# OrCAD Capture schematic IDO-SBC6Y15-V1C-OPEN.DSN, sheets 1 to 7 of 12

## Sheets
1 P01 NOTE: title: IDO-EVB6Y08-V1; note: NOTE
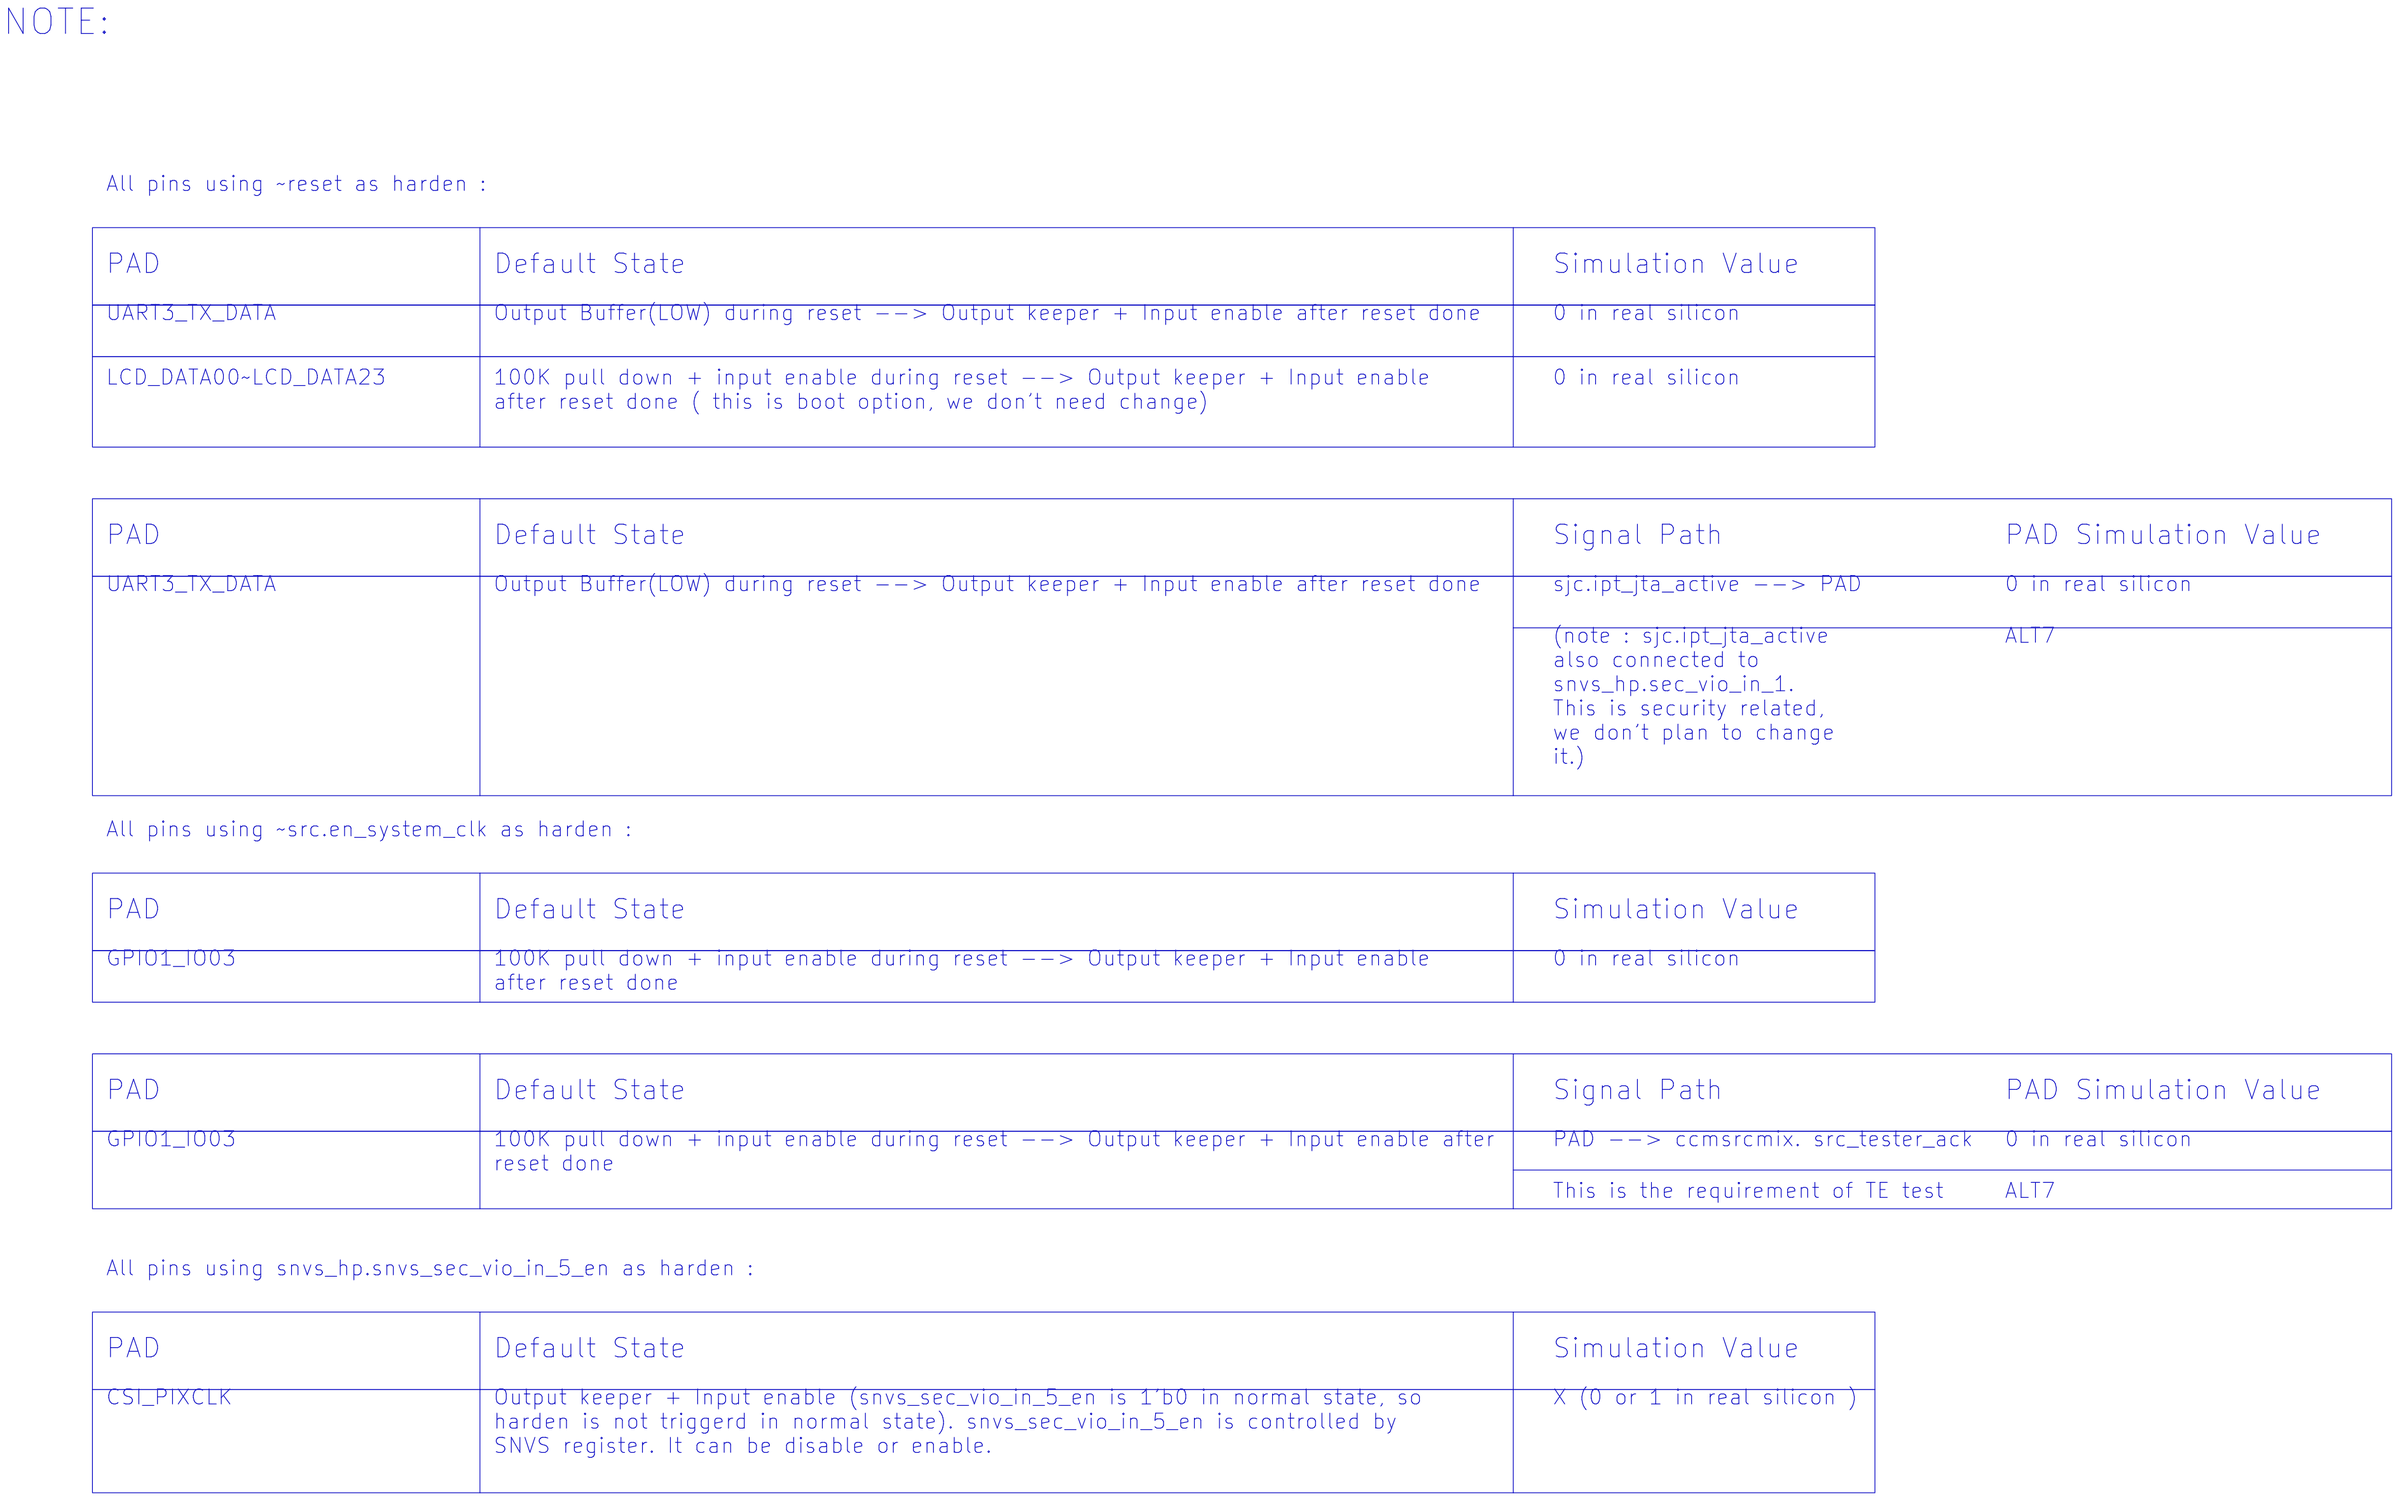
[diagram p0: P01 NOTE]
2 P02 IOMUX: note: IOMUX
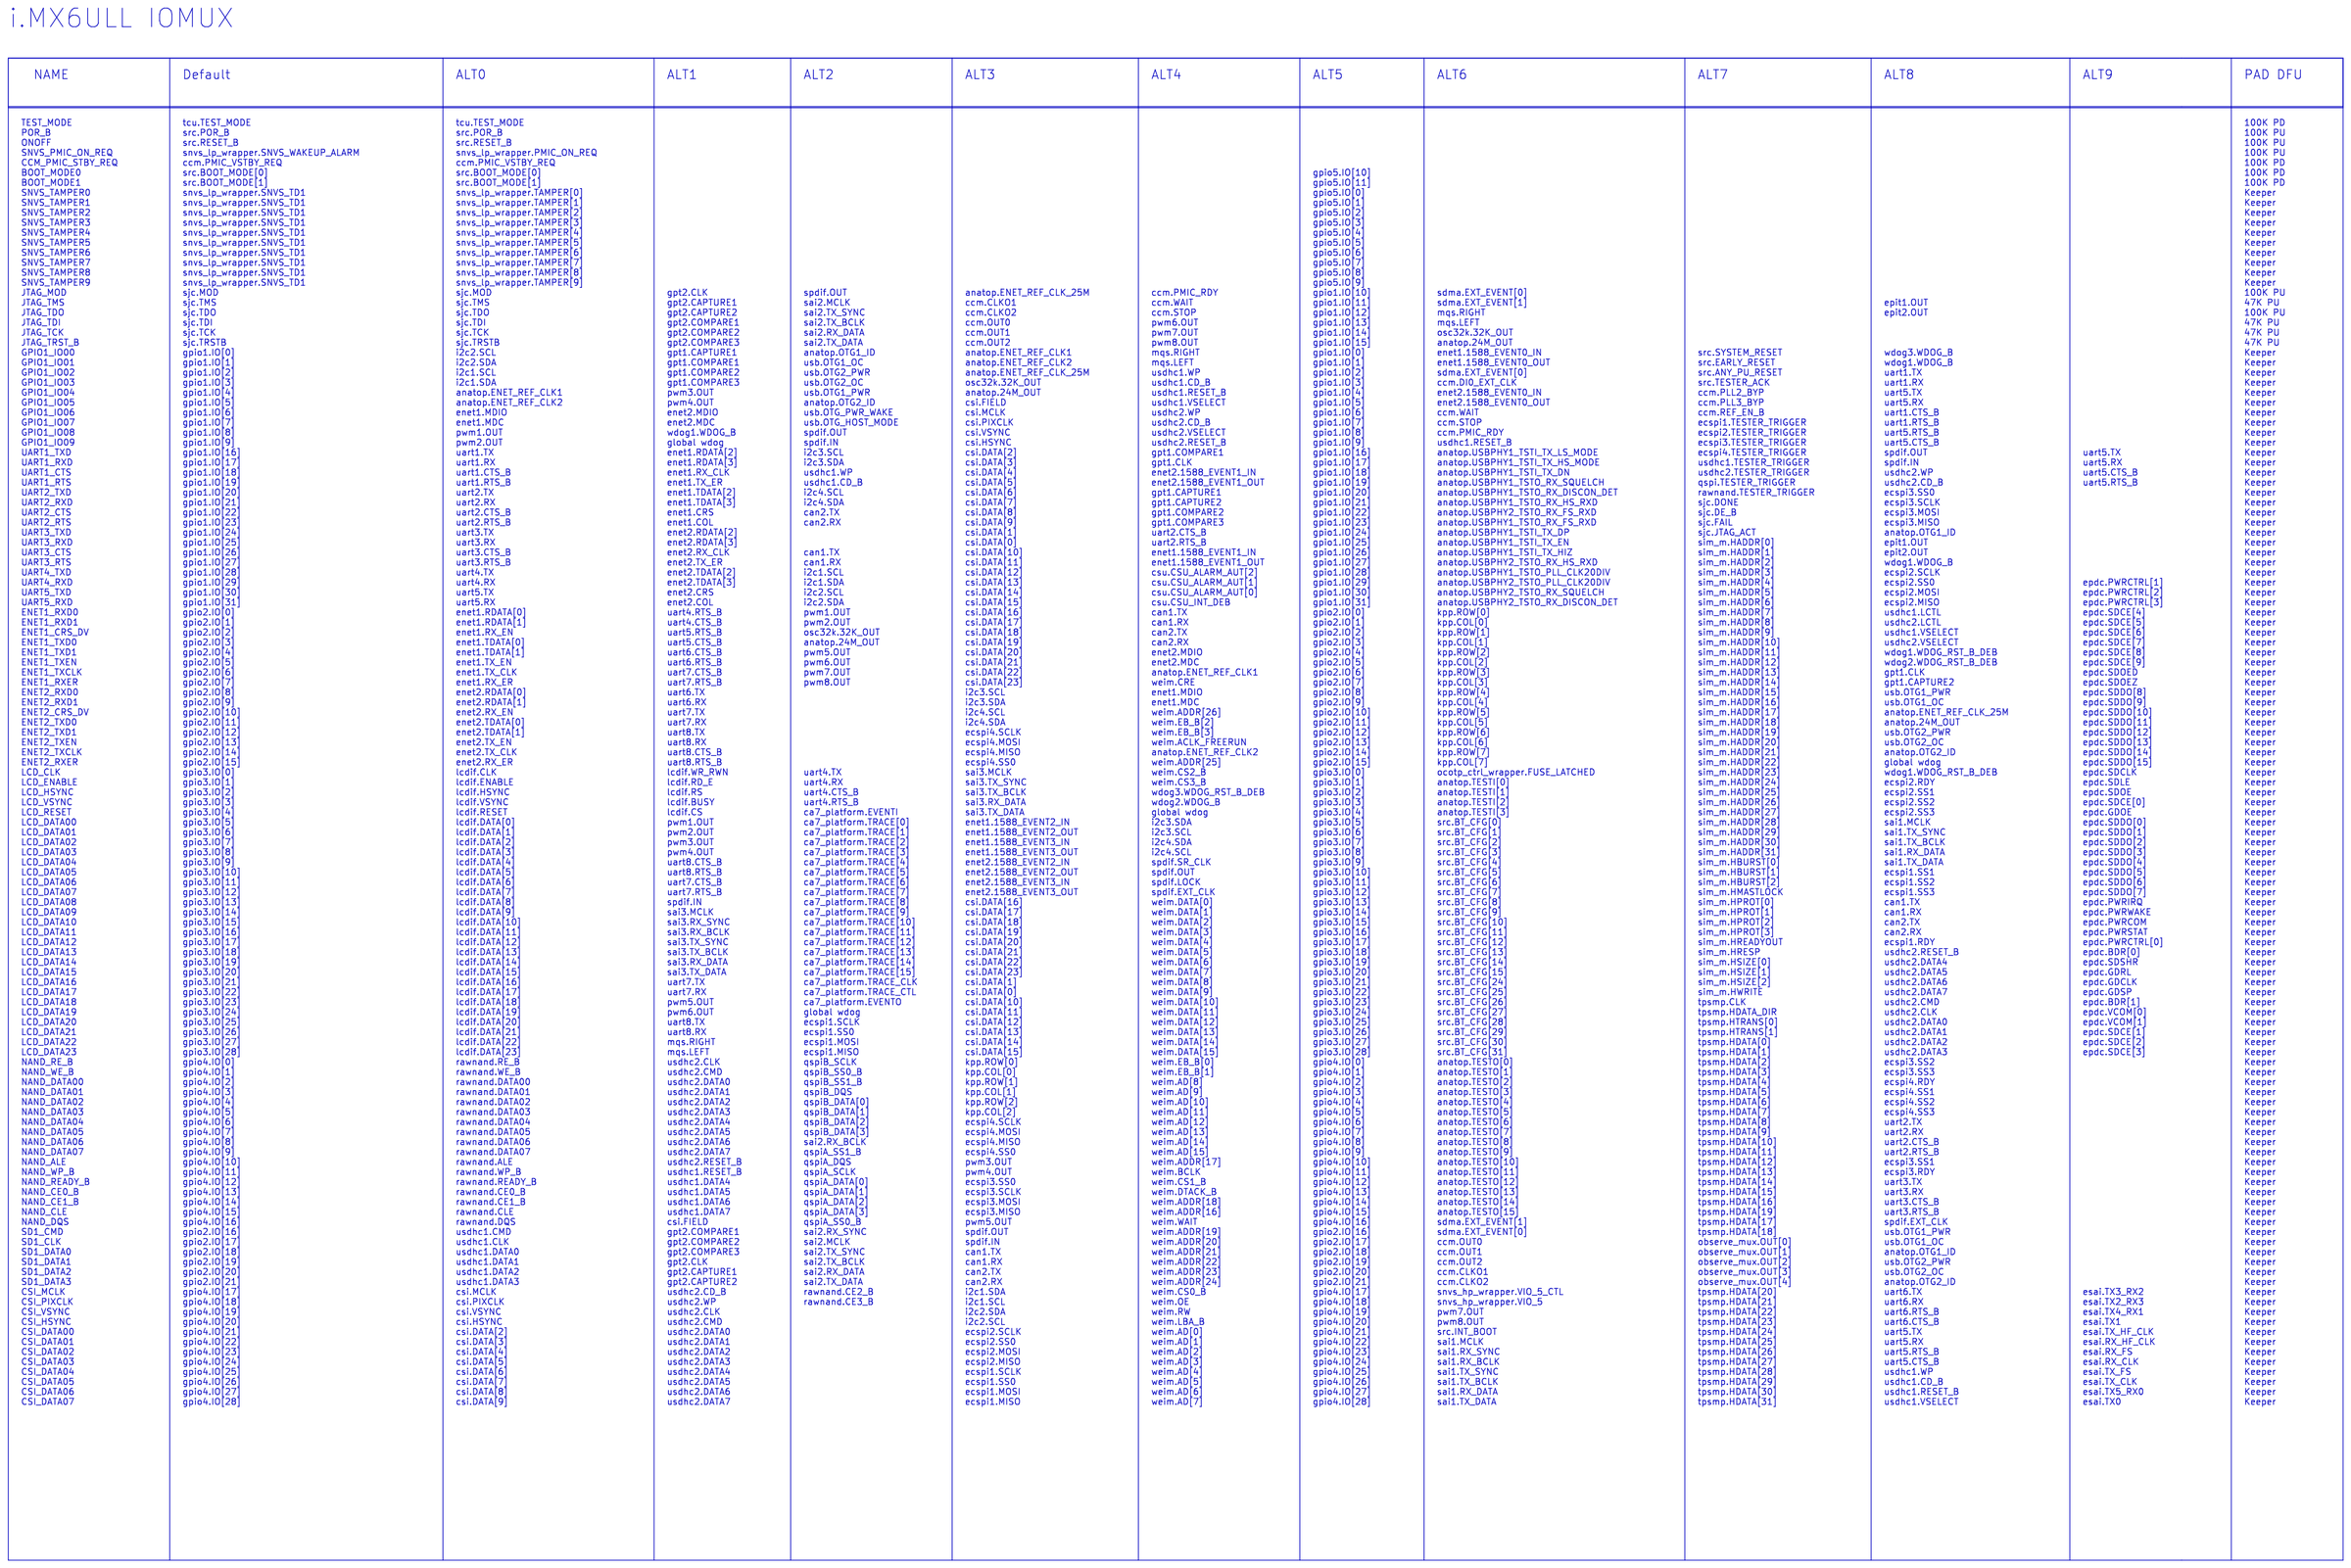
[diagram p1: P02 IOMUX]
3 P03 POWER TREE: note: POWER TREE
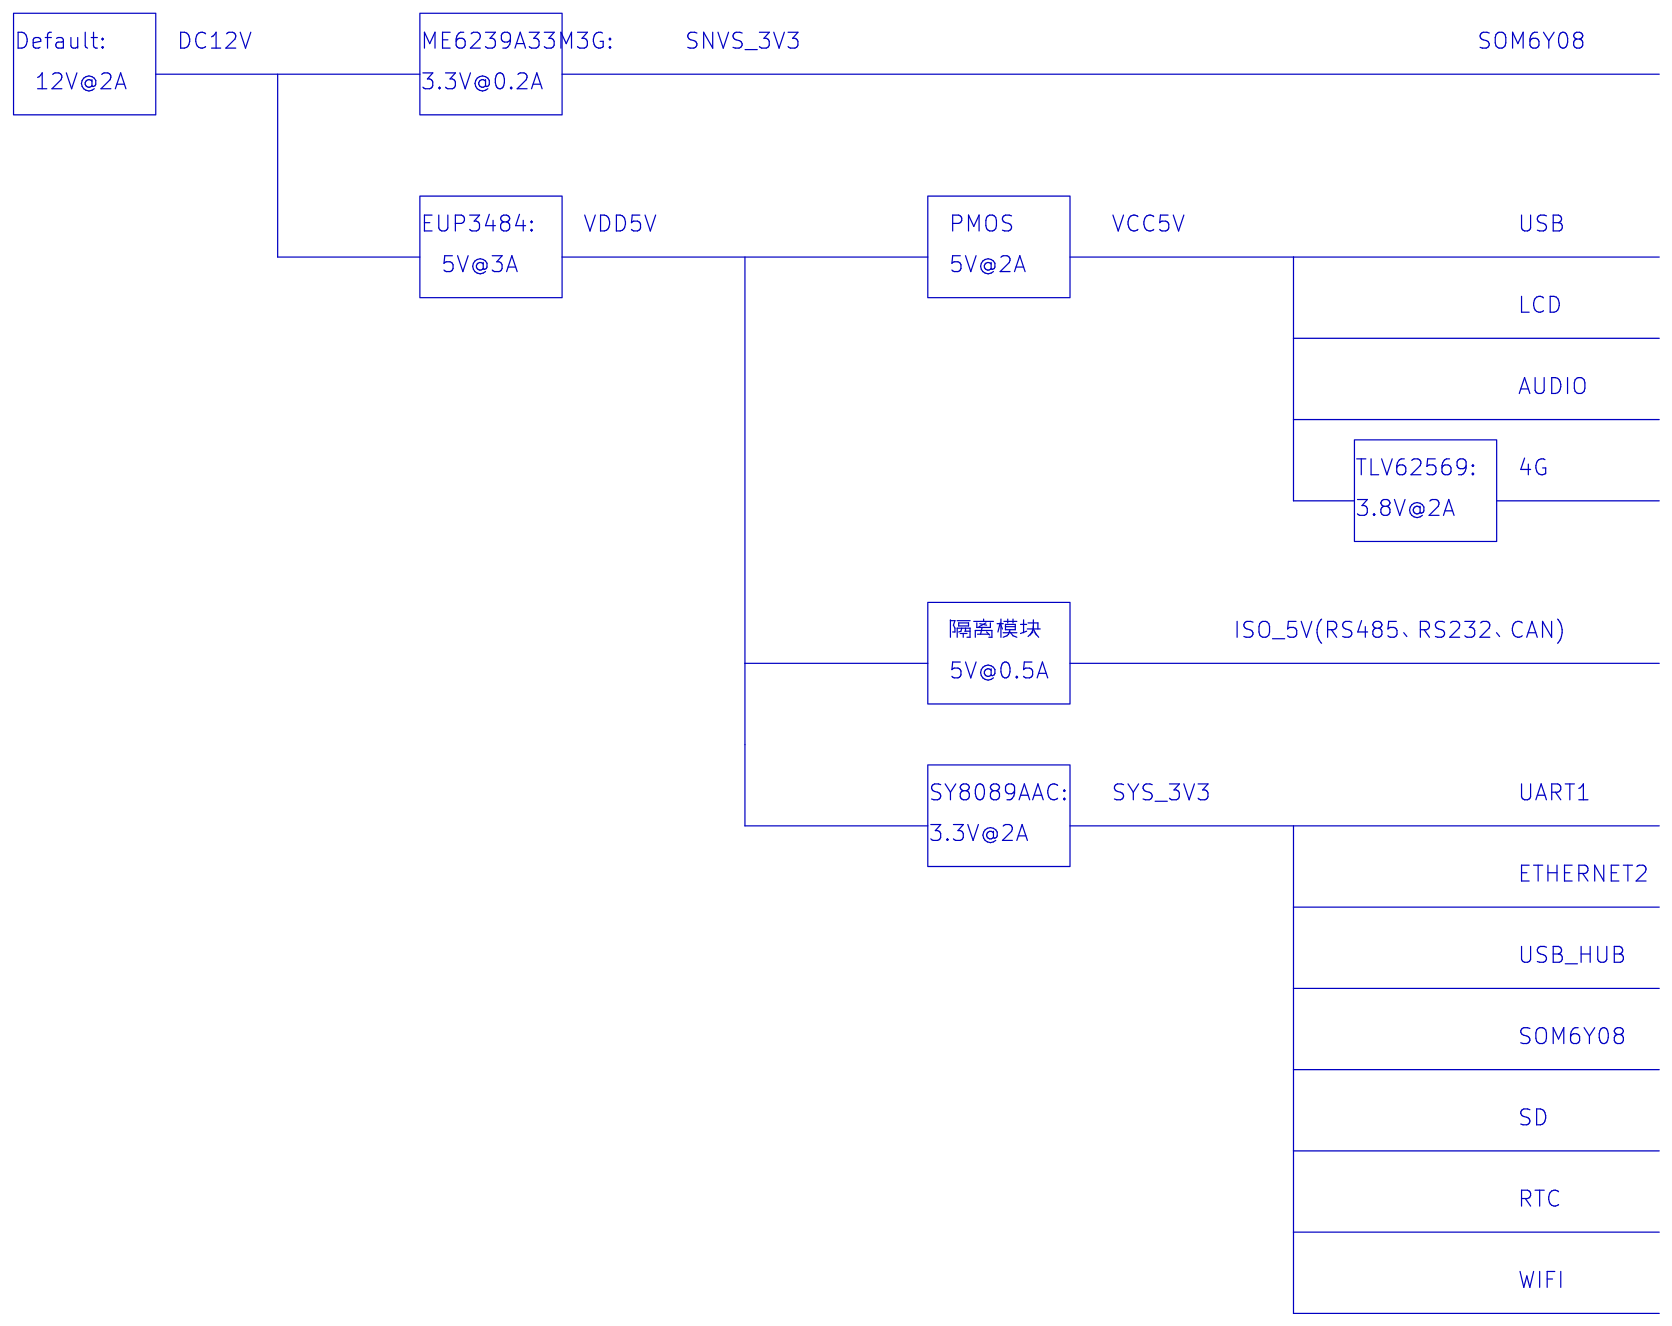
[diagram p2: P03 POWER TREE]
4 P04 BLOCK: note: BLOCK
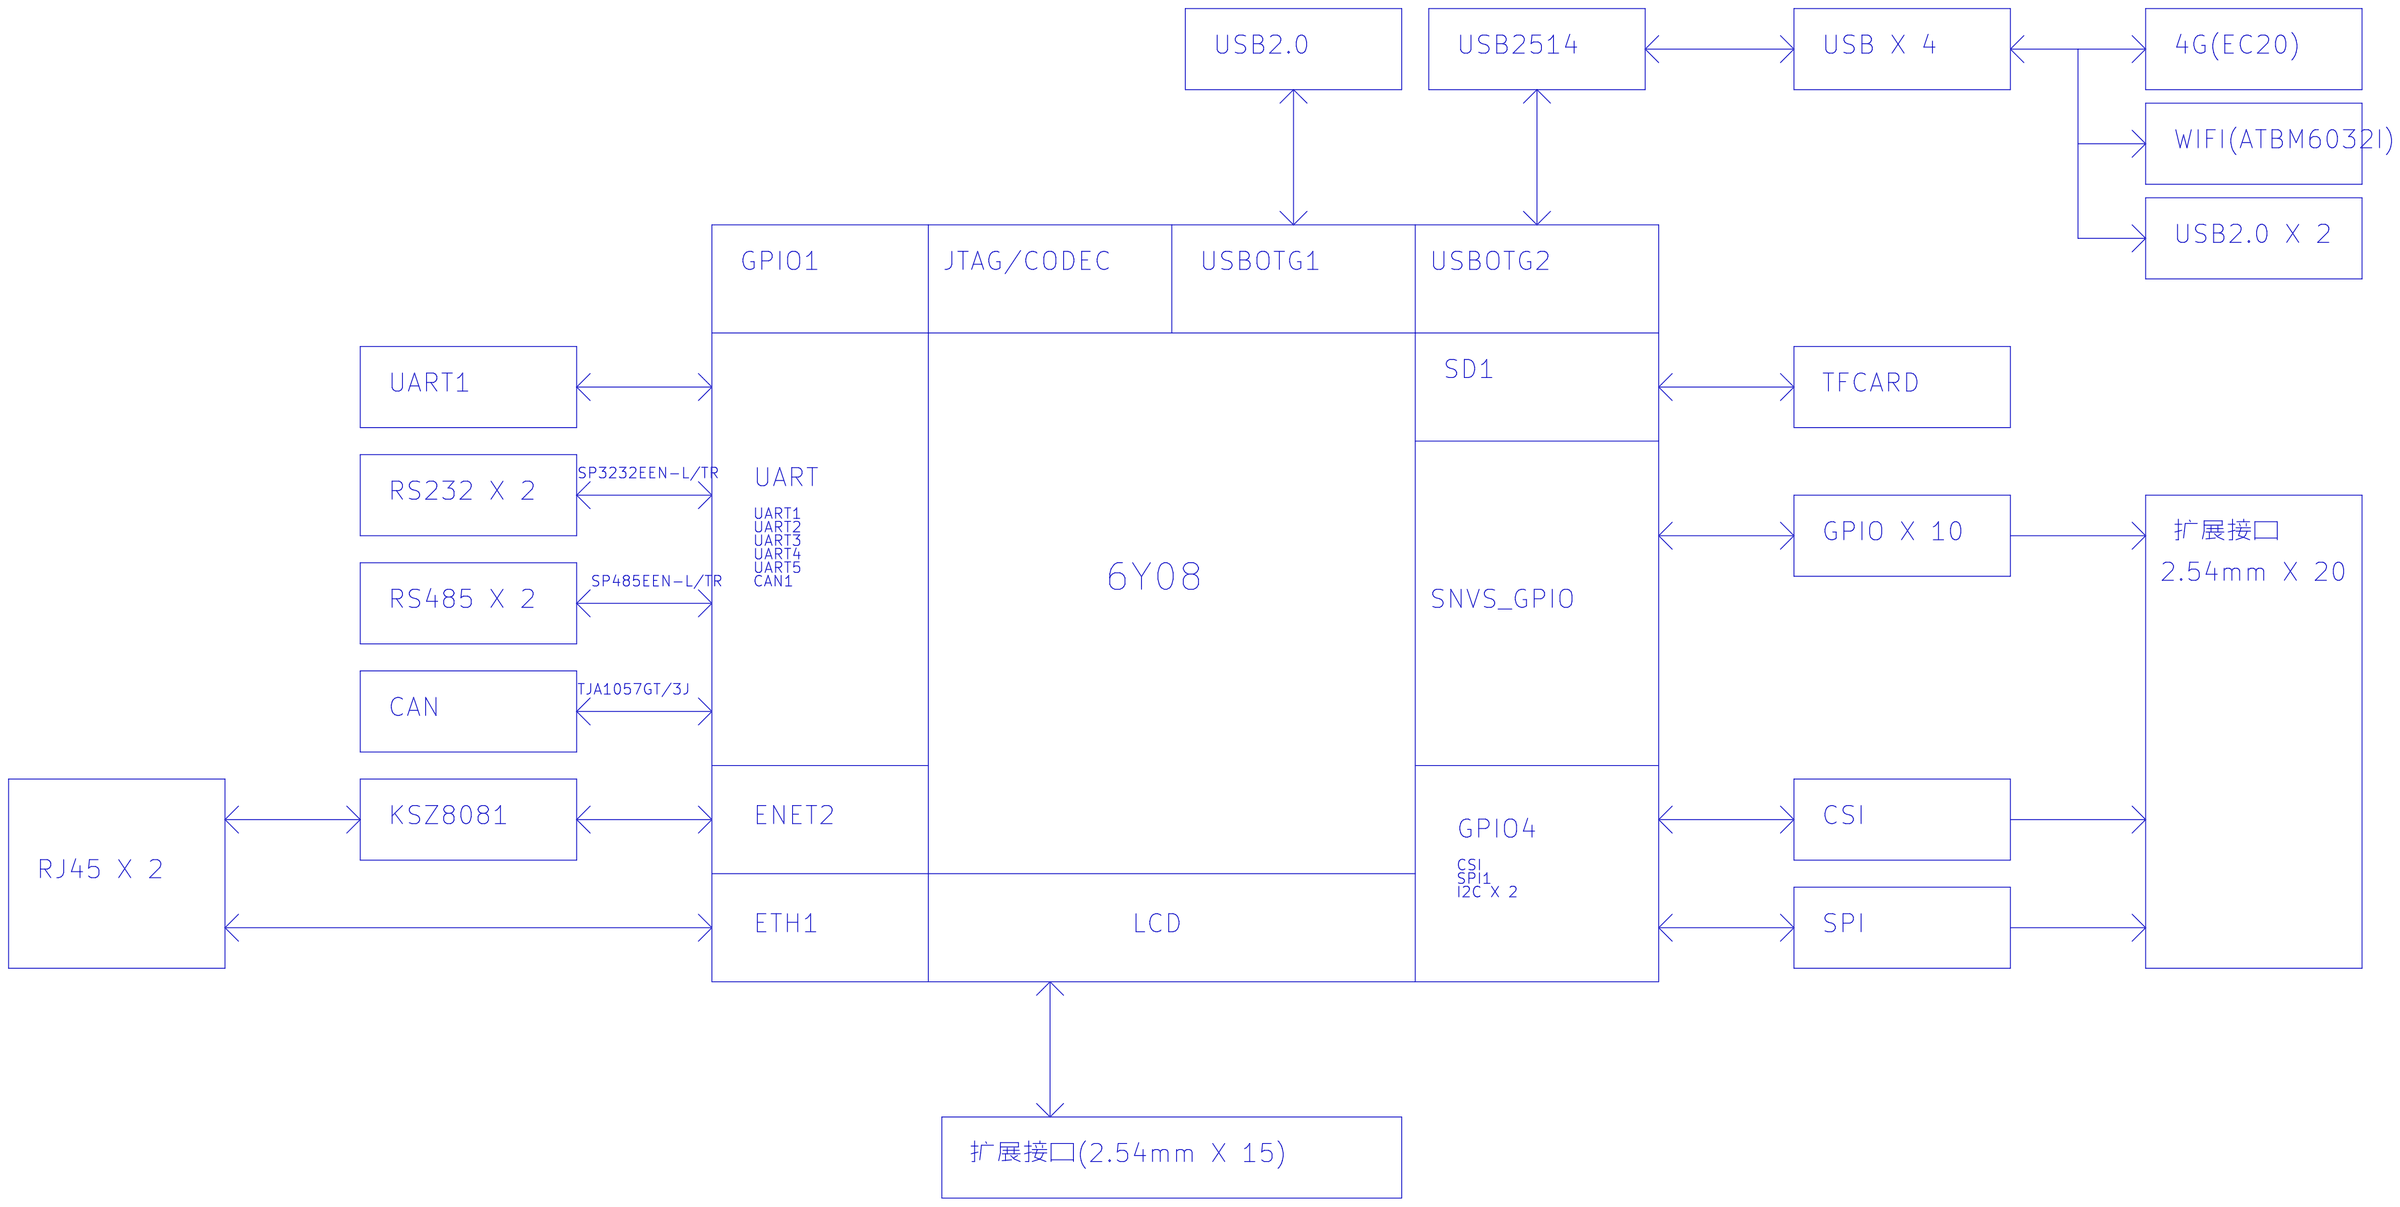
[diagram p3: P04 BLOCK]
5 P06 SOM6ULX: size A2; note: SOM6ULX
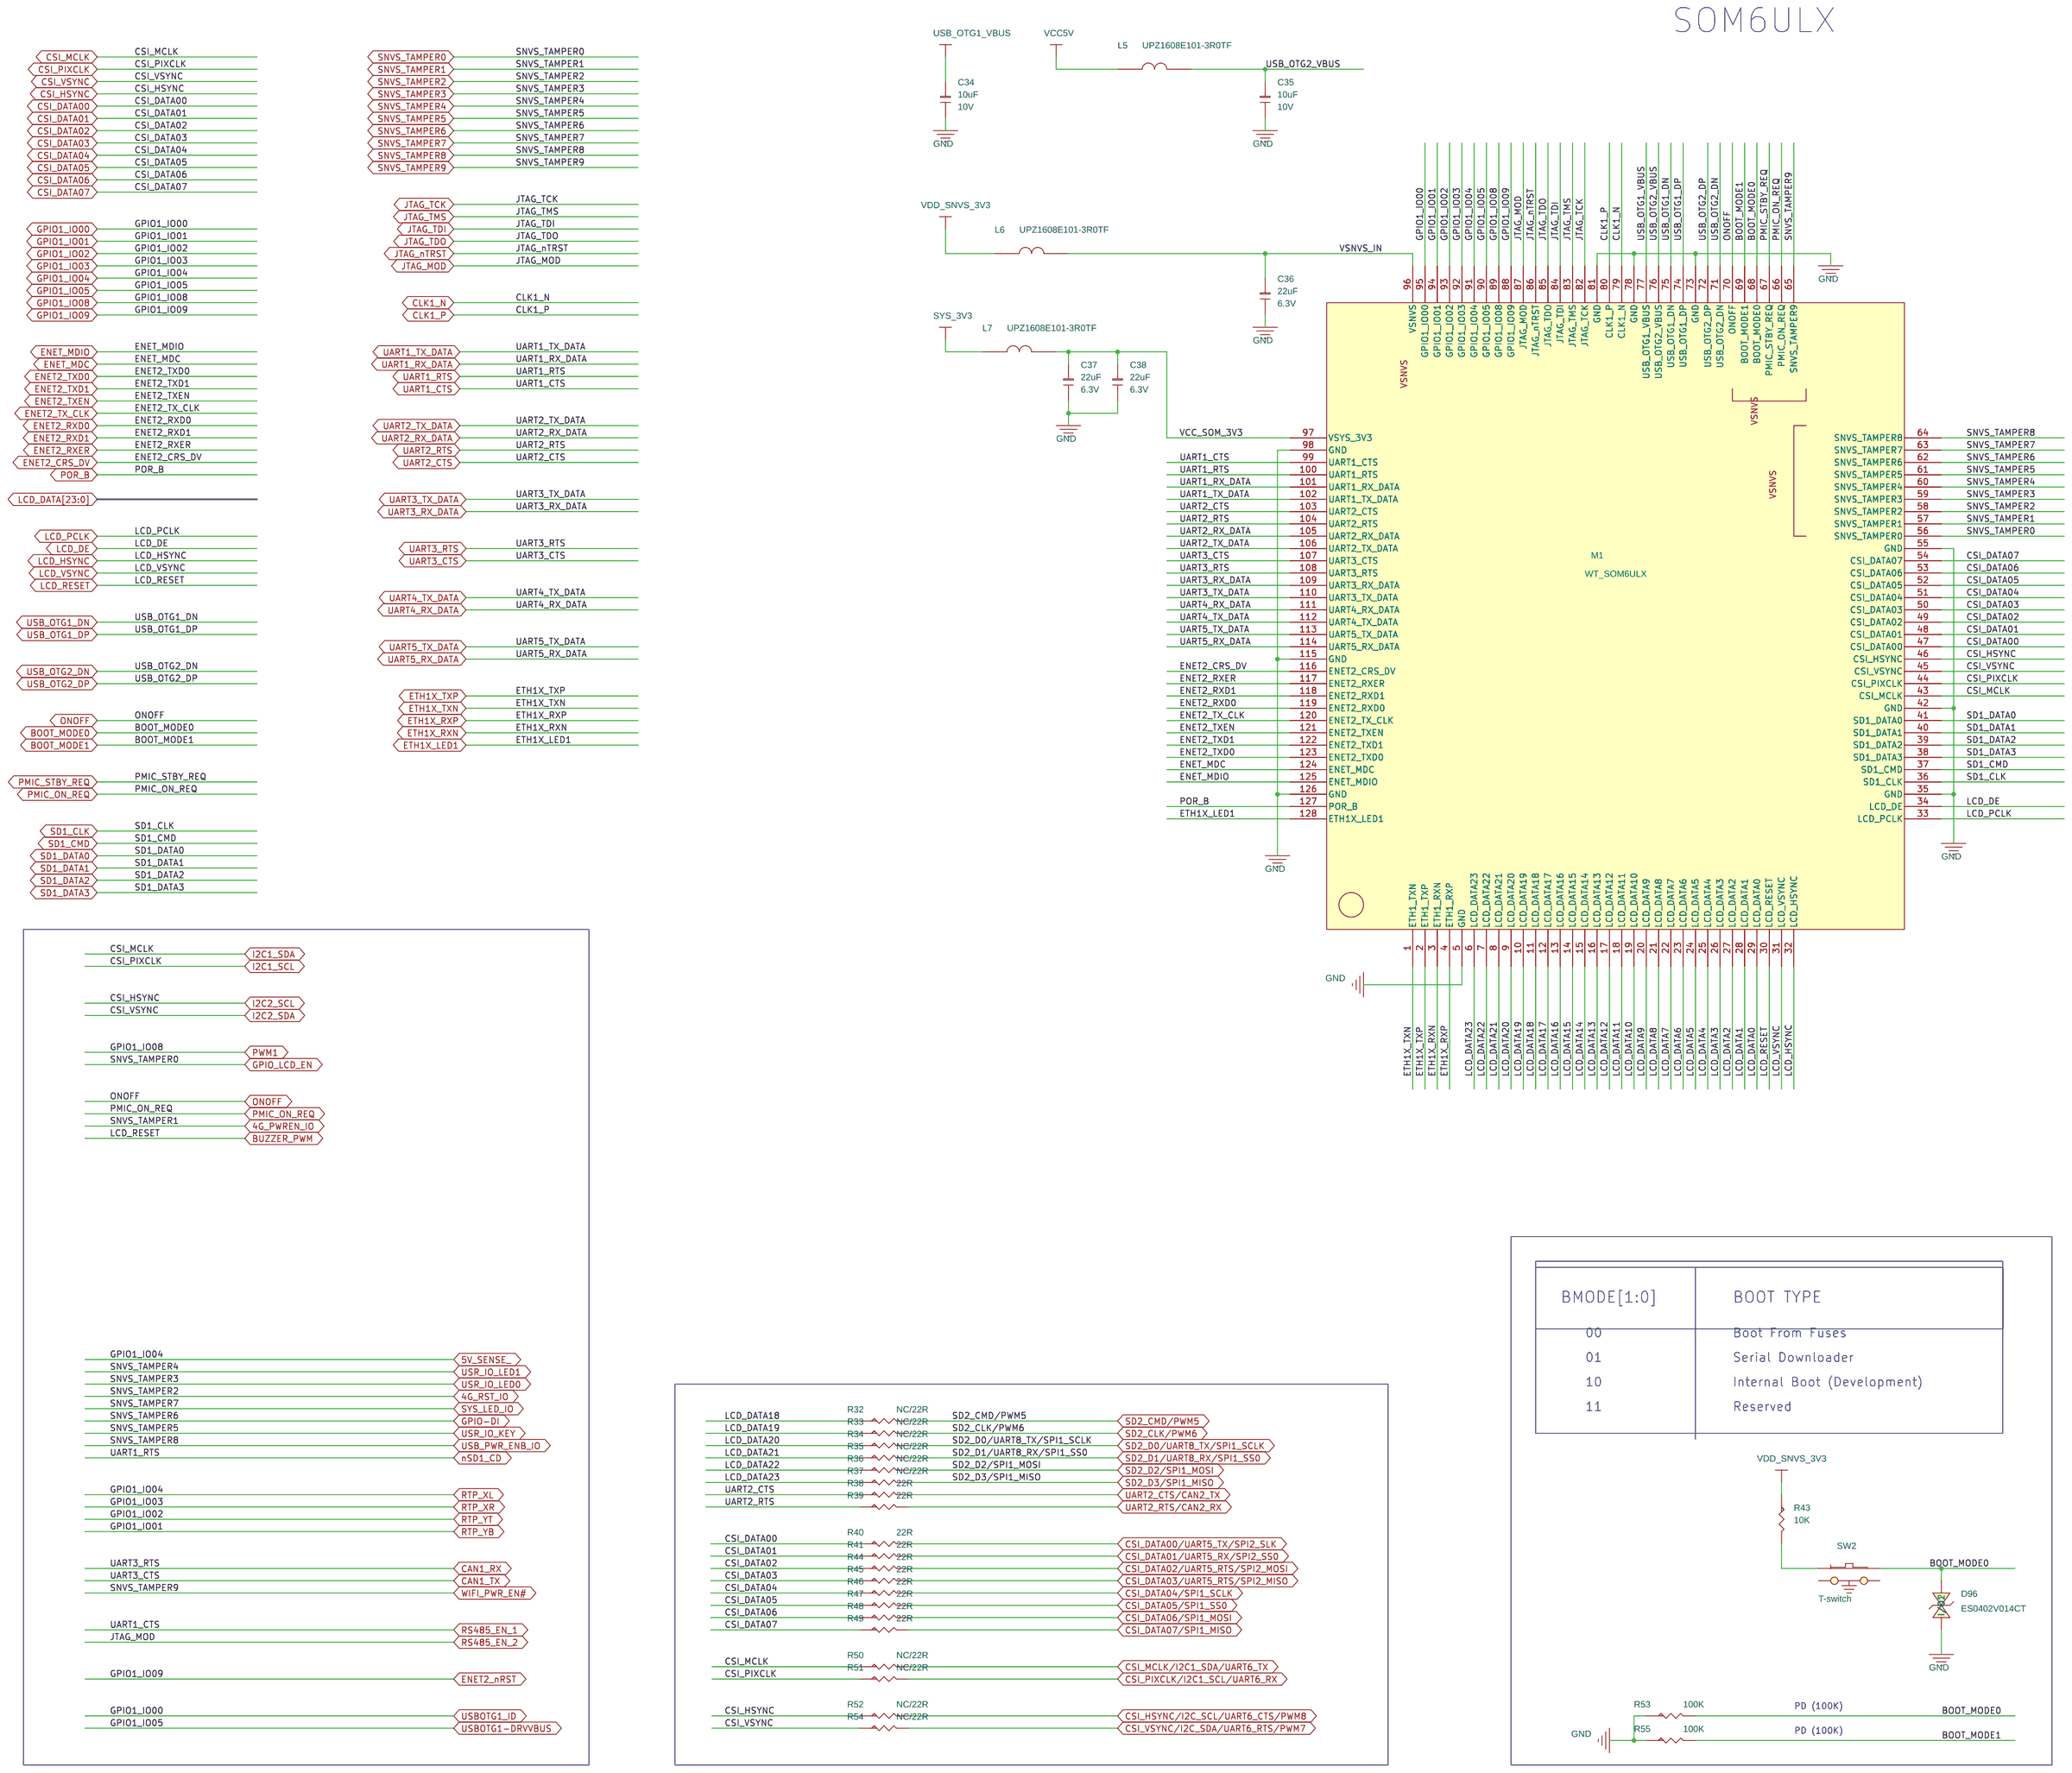
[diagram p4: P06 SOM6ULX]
6 P08 USB: size A2; note: USB
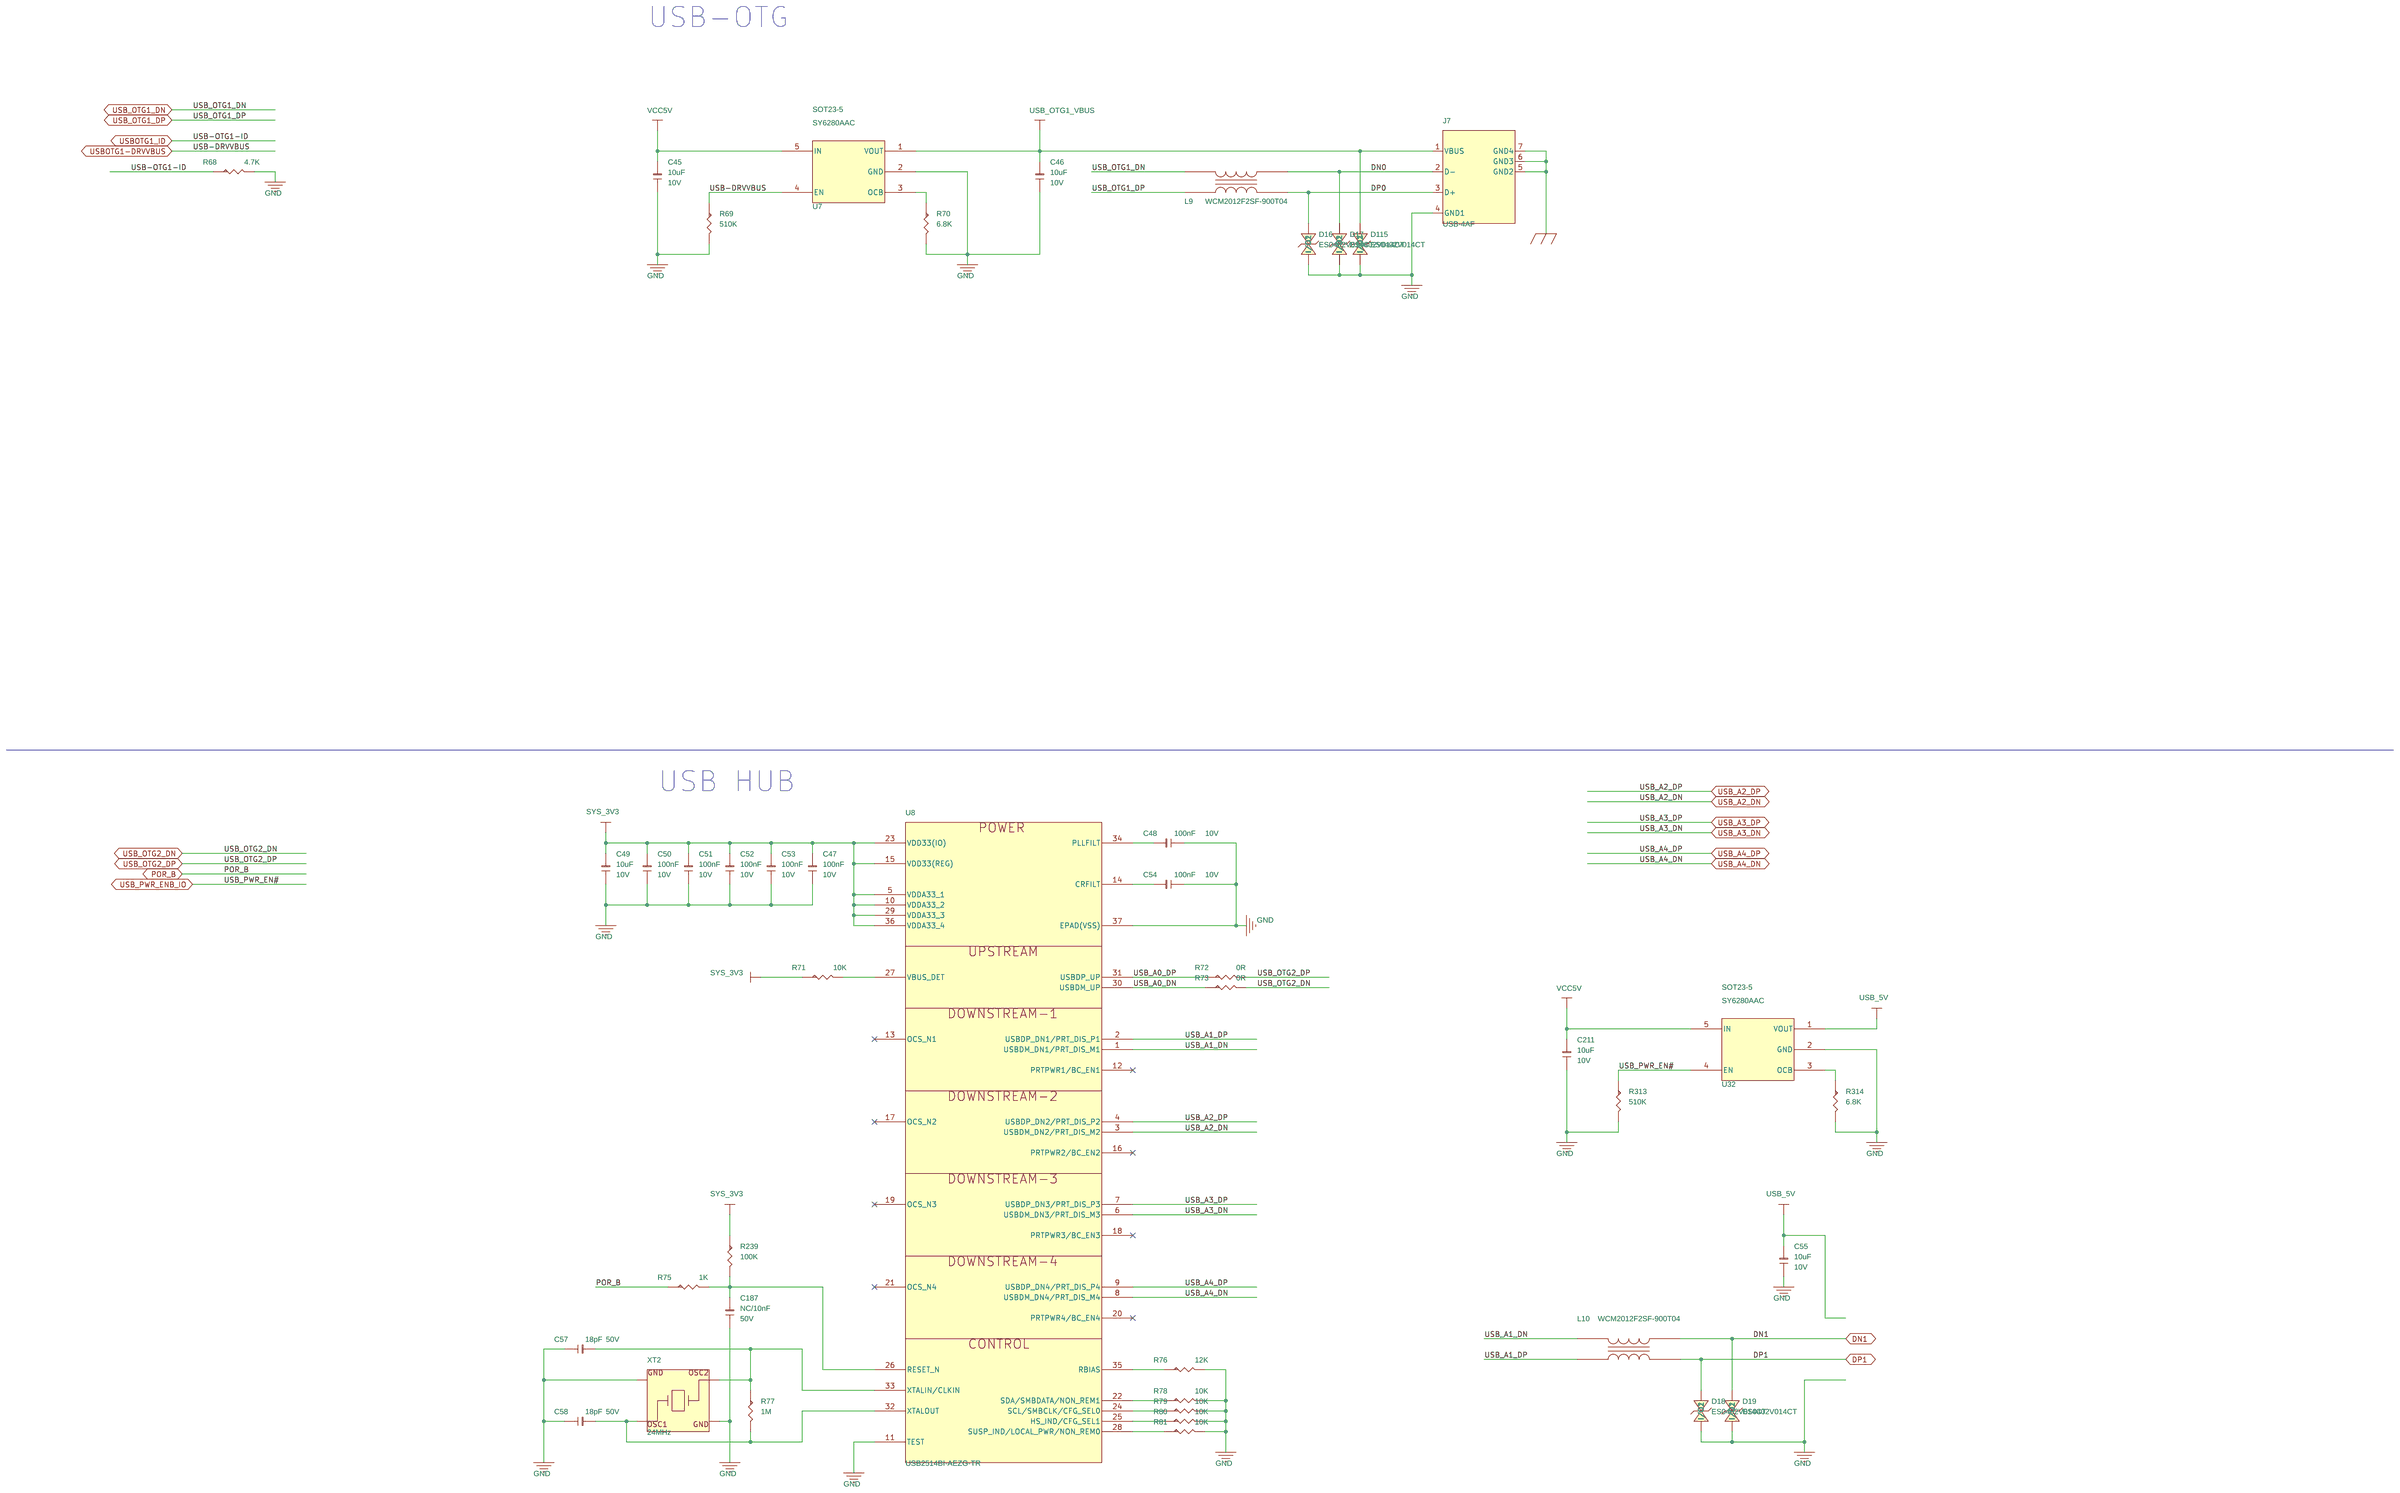
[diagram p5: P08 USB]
7 P09 ETHERNET: size A2; note: ETHERNET
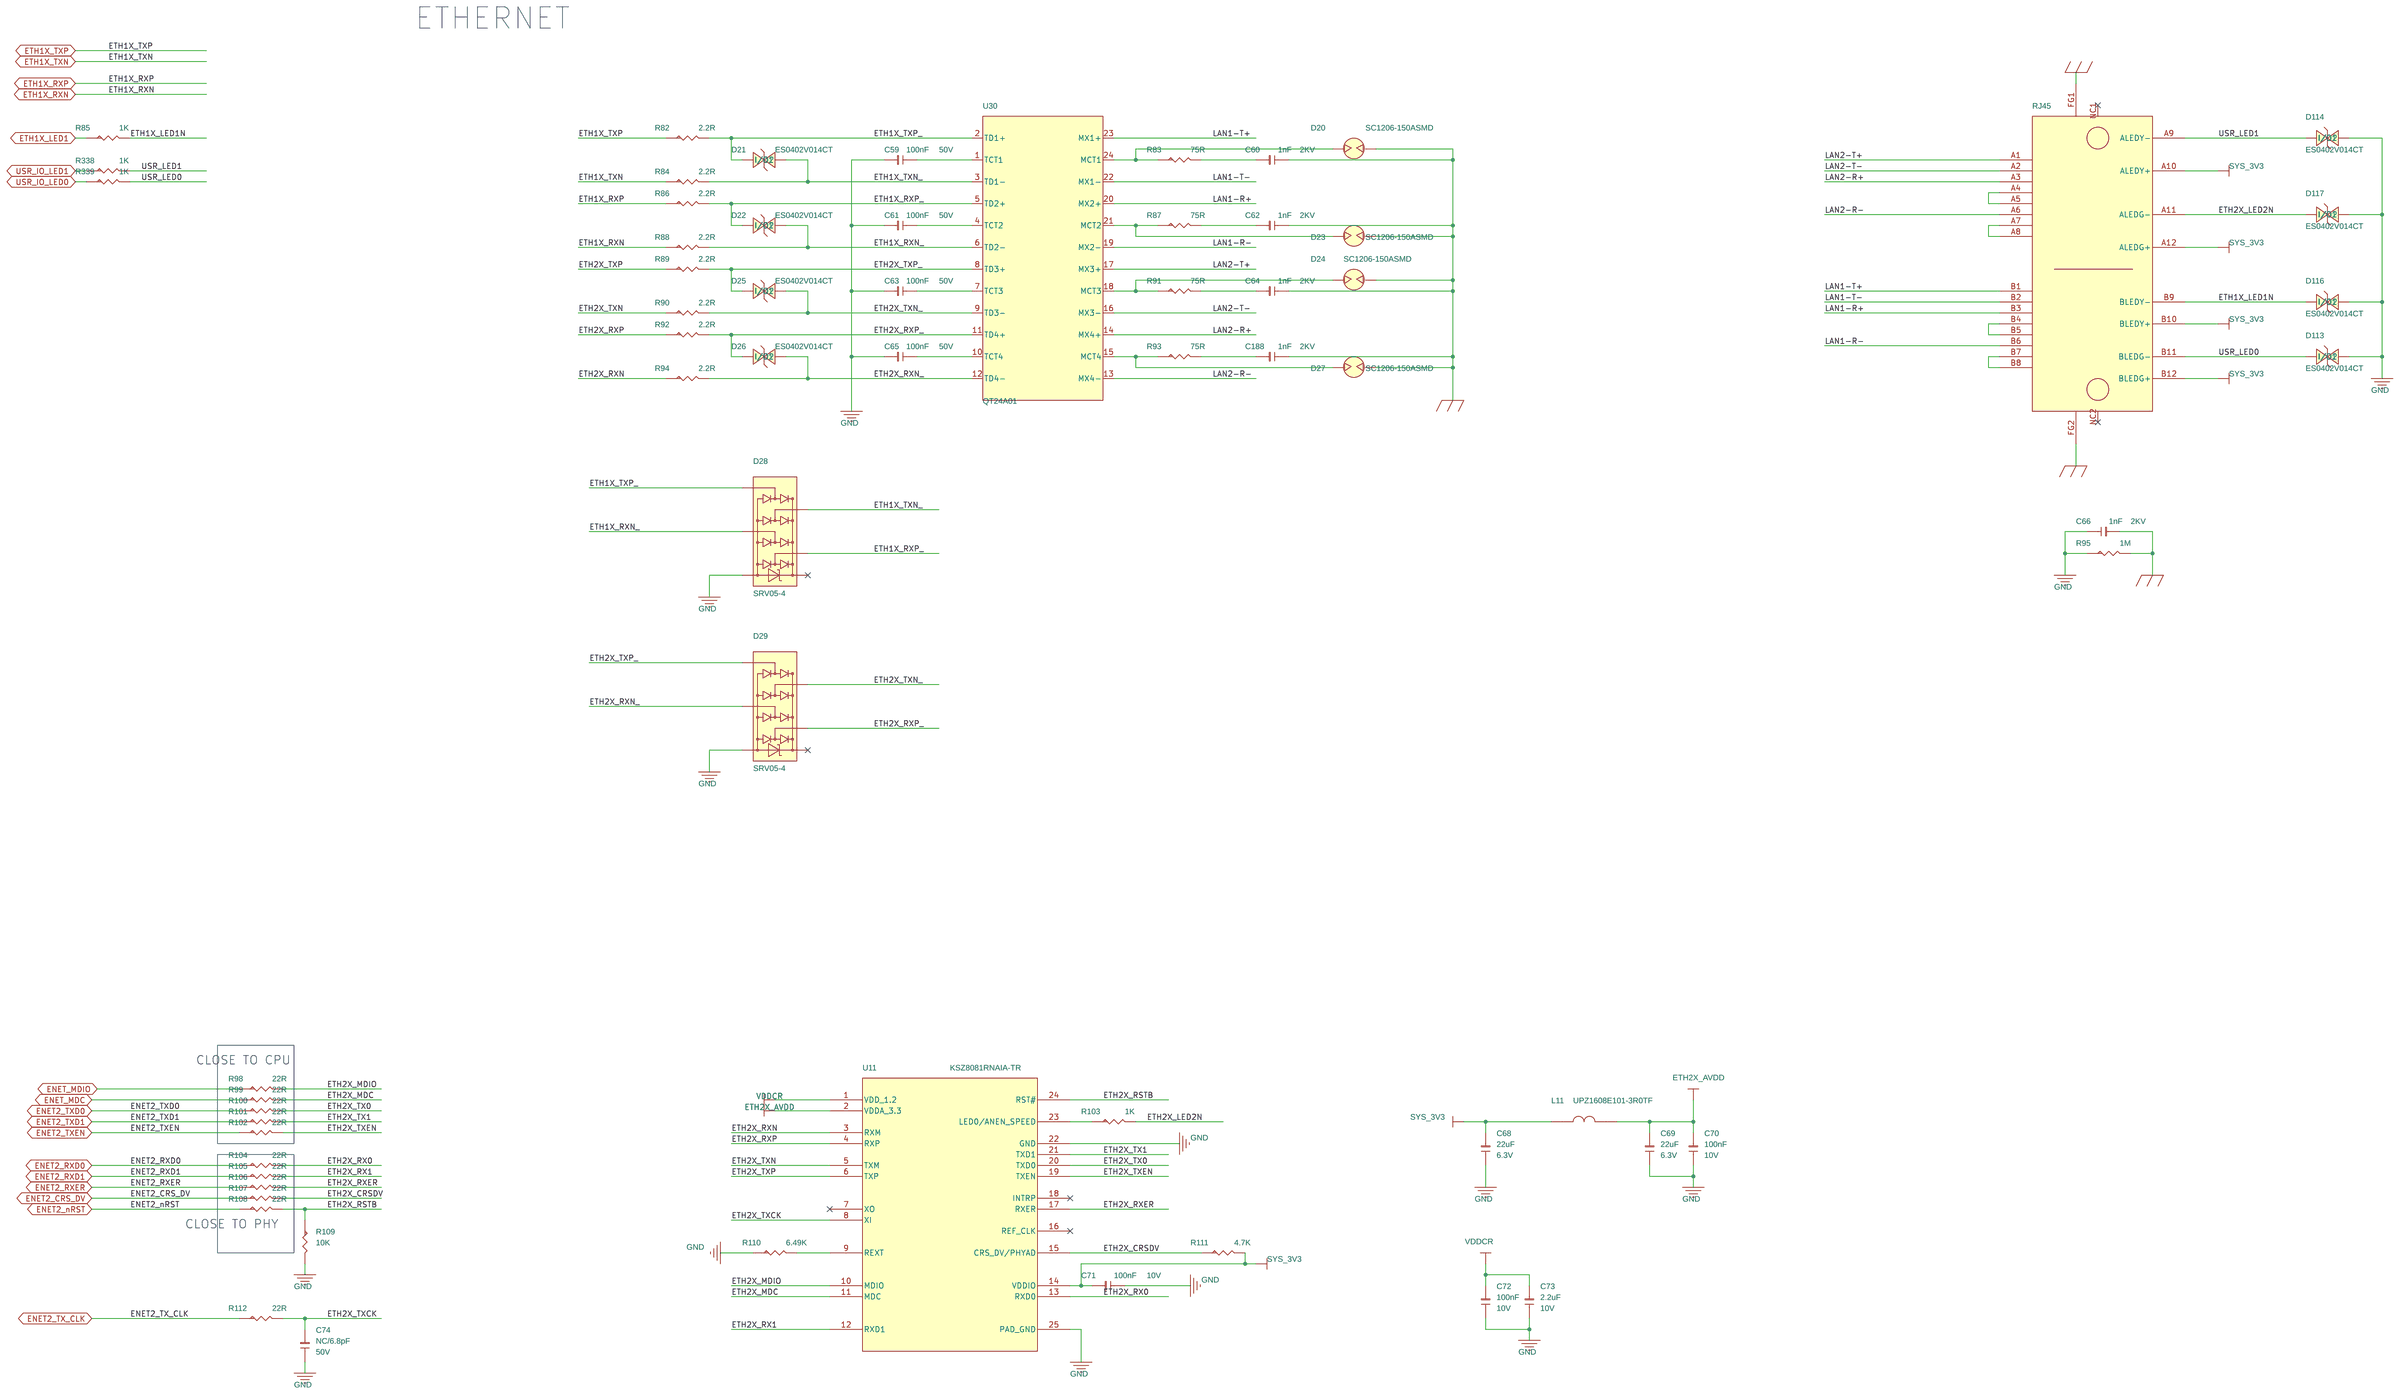
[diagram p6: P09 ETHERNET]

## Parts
sheet P06 SOM6ULX
C34  10uF  [C0603L]
C35  10uF  [C0603L]
C36  22uF  [C0603L]
C37  22uF  [C0603L]
C38  22uF  [C0603L]
D96  ES0402V014CT  [V0402]
L5  UPZ1608E101-3R0TF  [L0603]
L6  UPZ1608E101-3R0TF  [L0603]
L7  UPZ1608E101-3R0TF  [L0603]
M1  WT_SOM6ULX  [WT_SOM6ULX_LGA128]
R32  NC/22R  [R0402L]
R33  NC/22R  [R0402L]
R34  NC/22R  [R0402L]
R35  NC/22R  [R0402L]
R36  NC/22R  [R0402L]
R37  NC/22R  [R0402L]
R38  22R  [R0402L]
R39  22R  [R0402L]
R40  22R  [R0402L]
R41  22R  [R0402L]
R43  10K  [R0402L]
R44  22R  [R0402L]
R45  22R  [R0402L]
R46  22R  [R0402L]
R47  22R  [R0402L]
R48  22R  [R0402L]
R49  22R  [R0402L]
R50  NC/22R  [R0402L]
R51  NC/22R  [R0402L]
R52  NC/22R  [R0402L]
R53  100K  [R0402L]
R54  NC/22R  [R0402L]
R55  100K  [R0402L]
SW2  T-switch  [PB-SIDE-S-3x6]
sheet P08 USB
C45  10uF  [C0603L]
C46  10uF  [C0603L]
C47  100nF  [C0402L]
C48  100nF  [C0402L]
C49  10uF  [C0603L]
C50  100nF  [C0402L]
C51  100nF  [C0402L]
C52  100nF  [C0402L]
C53  100nF  [C0402L]
C54  100nF  [C0402L]
C55  10uF  [C0603L]
C57  18pF  [C0402L]
C58  18pF  [C0402L]
C187  NC/10nF  [C0402L]
C211  10uF  [C0603L]
D16  ES0402V014CT  [V0402]
D17  ES0402V014CT  [V0402]
D18  ES0402V014CT  [V0402]
D19  ES0402V014CT  [V0402]
D115  ES0402V014CT  [V0402]
J7  USB-4AF  [USB-4AF-DIP-3W]
L9  WCM2012F2SF-900T04  [CMLS-ACM2012]
L10  WCM2012F2SF-900T04  [CMLS-ACM2012]
R68  4.7K  [R0402L]
R69  510K  [R0402L]
R70  6.8K  [R0402L]
R71  10K  [R0402L]
R72  0R  [R0402L]
R73  0R  [R0402L]
R75  1K  [R0402L]
R76  12K  [R0402L]
R77  1M  [R0402L]
R78  10K  [R0402L]
R79  10K  [R0402L]
R80  10K  [R0402L]
R81  10K  [R0402L]
R239  100K  [R0402L]
R313  510K  [R0402L]
R314  6.8K  [R0402L]
U7  SY6280AAC  [SOT23-5]
U8  USB2514BI-AEZG-TR  [USB2514BI-QFN-36]
U32  SY6280AAC  [SOT23-5]
XT2  24MHz  [xtal_32x25_4p]
sheet P09 ETHERNET
C59  100nF  [C0402L]
C60  1nF  [C1206L]
C61  100nF  [C0402L]
C62  1nF  [C1206L]
C63  100nF  [C0402L]
C64  1nF  [C1206L]
C65  100nF  [C0402L]
C66  1nF  [C1206L]
C68  22uF  [C0603L]
C69  22uF  [C0603L]
C70  100nF  [C0402L]
C71  100nF  [C0402L]
C72  100nF  [C0402L]
C73  2.2uF  [C0402L]
C74  NC/6.8pF  [C0402L]
C188  1nF  [C1206L]
D20  SC1206-150ASMD  [SMD1206]
D21  ES0402V014CT  [V0402]
D22  ES0402V014CT  [V0402]
D23  SC1206-150ASMD  [SMD1206]
D24  SC1206-150ASMD  [SMD1206]
D25  ES0402V014CT  [V0402]
D26  ES0402V014CT  [V0402]
D27  SC1206-150ASMD  [SMD1206]
D28  SRV05-4  [SOT23-6]
D29  SRV05-4  [SOT23-6]
D113  ES0402V014CT  [V0402]
D114  ES0402V014CT  [V0402]
D116  ES0402V014CT  [V0402]
D117  ES0402V014CT  [V0402]
J55  RJ45  [RJ45-1X2-8P8C-R-LED]
L11  UPZ1608E101-3R0TF  [L0603]
R82  2.2R  [R0402L]
R83  75R  [R0603L]
R84  2.2R  [R0402L]
R85  1K  [R0402L]
R86  2.2R  [R0402L]
R87  75R  [R0603L]
R88  2.2R  [R0402L]
R89  2.2R  [R0402L]
R90  2.2R  [R0402L]
R91  75R  [R0603L]
R92  2.2R  [R0402L]
R93  75R  [R0603L]
R94  2.2R  [R0402L]
R95  1M  [R0805L]
R98  22R  [R0402L]
R99  22R  [R0402L]
R100  22R  [R0402L]
R101  22R  [R0402L]
R102  22R  [R0402L]
R103  1K  [R0402L]
R104  22R  [R0402L]
R105  22R  [R0402L]
R106  22R  [R0402L]
R107  22R  [R0402L]
R108  22R  [R0402L]
R109  10K  [R0402L]
R110  6.49K  [R0402L]
R111  4.7K  [R0402L]
R112  22R  [R0402L]
R338  1K  [R0402L]
R339  1K  [R0402L]
U11  KSZ8081RNAIA-TR  [KSZ8081RNAIA-QFN-24]
U30  QT24A01  [QT24A01-SOP24]

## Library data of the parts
C34 C35 C45 C46 C49 C55 C211 = C-0603: DSC1: ±20%; DSC2: 10V; DSC3: X5R; ERP Number: 1010200076; ID: 71; Manufacture: 三星|国巨|村田; Part Name: 贴片电容; Part Number: C020102120071; Price: 0.05
C36-C38 C68 C69 = C-0603: DSC1: ±20%; DSC2: 6.3V; DSC3: X5R; ERP Number: 1010200133; ID: 72; Manufacture: 三星|国巨|村田; Part Name: 贴片电容; Part Number: C020102120072; Price: 0.06
D16-D19 D21 D22 D25 D26 D96 D113-D117 = DI-ESD: DSC1: 双向; DSC2: Vdc=14V; DSC3: Vbr=300V; DSC4: Vc=30V; DSC5: Cj=0.25pF; ERP Number: 1010800023; ID: 2; Manufacture: AEM; Part Name: ESD; Part Number: C040502250002; Price: 0.06
L5-L7 L11 = FB-0603: DSC1: 100Ω@100MHz; DSC2: 3A; DSC3: DCR=30mΩ; DSC4: 电源线; ERP Number: 1010200207; ID: 5; Manufacture: 顺络; Part Name: 贴片磁珠; Part Number: C060502370005; Price: 0.03
M1 = IDO-SOM6Y08
R32-R41 R44-R52 R54 R98-R102 R104-R108 R112 = R-0402: DSC1: ±1%; DSC2: 1/16W; ID: 552; Part Name: 贴片电阻; Part Number: C011002080552; Price: 0.01
R43 R71 R78-R81 R109 = R-0402: DSC1: ±1%; DSC2: 1/16W; ERP Number: 1010200140; ID: 856; Part Name: 贴片电阻; Part Number: C011002080856; Price: 0.01
R53 R55 R239 = R-0402: DSC1: ±1%; DSC2: 1/16W; ERP Number: 1010200137; ID: 976; Part Name: 贴片电阻; Part Number: C011002080976; Price: 0.01
SW2 = SW-TS36CA: DSC1: 轻触开关 侧键 贴片 带定位柱; DSC2: SMD,3.5*7.7mm; DSC3: TS36CA-0.7(首韩); DSC4: TSA365G00D-250(博瑞泰); ID: 2; Part Name: 轻触开关; Part Number: C180102690002
C47 C48 C50-C54 C70-C72 = C-0402: DSC1: ±10%; DSC2: 10V; DSC3: X7R; ID: 60; Manufacture: 三星|国巨|村田; Part Name: 贴片电容; Part Number: C020102120060; Price: 0.01
C57 C58 = C-0402: DSC1: ±5%; DSC2: 50V; DSC3: C0G; ERP Number: 1010200091; ID: 27; Manufacture: 三星|国巨|村田; Part Name: 贴片电容; Part Number: C020102120027; Price: 0.02
C187 = C-0402: DSC1: ±10%; DSC2: 50V; DSC3: X7R; ERP Number: 1010200077; ID: 57; Manufacture: 三星|国巨|村田; Part Name: 贴片电容; Part Number: C020102120057; Price: 0.02
J7 = J-USB-4AF-DIP-W-3_1: DSC1: USB AF 90度 侧插 铁壳短体10.4 无卷边 白胶; DSC2: 10.4*5.7mm*13.1; DSC3: 通孔弯针; DSC4: C42684(LC); ID: 7; Part Name: USB连接器; Part Number: J060102960007
L9 L10 = L-CMLS-ACM2012: DSC1: 90uH@100kHz; DSC2: 90Ω@100MHz; DSC3: 400mA; DSC4: DCR=300mΩ; DSC5: -40℃ ~ +125℃; DSC6: SMD_4P,2x1.2mm; ERP Number: 1010200196; ID: 1; Manufacture: 台庆; Part Name: 信号共模电感; Part Number: C060402360001; Price: 0.13
R68 R111 = R-0402: DSC1: ±1%; DSC2: 1/16W; ERP Number: 1010200445; ID: 818; Part Name: 贴片电阻; Part Number: C011002080818; Price: 0.01
R69 R313 = R-0402: DSC1: ±1%; DSC2: 1/16W; ERP Number: 1010200459; ID: 1,059; Part Name: 贴片电阻; Part Number: C011002081059; Price: 0.01
R70 R314 = R-0402: DSC1: ±1%; DSC2: 1/16W; ERP Number: 1010200334; ID: 837; Part Name: 贴片电阻; Part Number: C011002080837; Price: 0.01
R72 R73 = R-0402: DSC1: ±1%; DSC2: 1/16W; ID: 413; Part Name: 贴片电阻; Part Number: C011002080413; Price: 0.01
R75 R85 R103 R338 R339 = R-0402: DSC1: ±1%; DSC2: 1/16W; ERP Number: 1010200113; ID: 742; Part Name: 贴片电阻; Part Number: C011002080742; Price: 0.01
R76 = R-0402: DSC1: ±1%; DSC2: 1/16W; ERP Number: 1010200060; ID: 864; Part Name: 贴片电阻; Part Number: C011002080864; Price: 0.01
R77 = R-0402: DSC1: ±1%; DSC2: 1/16W; ERP Number: 1010200470; ID: 1,093; Part Name: 贴片电阻; Part Number: C011002081093; Price: 0.01
U7 U32 = U-SY6280AAC: DSC1: 低能耗电源开关; DSC2: 2.4-5.5V 2A; DSC3: 80m?; DSC4: -40~85℃; ERP Number: 1010100222; ID: 1; Manufacture: 矽力杰; Part Name: 功率开关; Part Number: C070402430001; Price: 0.42
U8 = U-USB2514BI-AEZG-TR: DSC1: USB2.0 HUB 4Ports Industrial; DSC2: QFN36，6mm×6mm，0.5mm Pitch; DSC3: -40℃~+85℃; ERP Number: 1010100144; ID: 12; Manufacture: MICROCHIP(美国微芯); Part Name: USB芯片; Part Number: C100202500001; Price: 10
XT2 = XTAL-4P: DSC1: 40Ω; DSC2: ±10ppm; DSC3: 12pF; DSC4: -40℃~+85℃; DSC5: 3.2*2.5mm 4P; ID: 5; Manufacture: 泰晶; Part Name: 贴片无源晶振; Part Number: C050102290005; Price: 0.45
C59 C61 C63 C65 = C-0402: DSC1: ±10%; DSC2: 50V; DSC3: X7R; ERP Number: 1010200128; ID: 61; Manufacture: 三星|国巨|村田; Part Name: 贴片电容; Part Number: C020102120061; Price: 0.05
C60 C62 C64 C66 C188 = C-1206: DSC1: ±10%; DSC2: 2KV; DSC3: X7R; ERP Number: 1010200094; ID: 77; Manufacture: 三星|国巨|村田; Part Name: 贴片电容; Part Number: C020102120077; Price: 0.17
C73 = C-0402: DSC1: ±10%; DSC2: 10V; DSC3: X5R; ID: 66; Manufacture: 三星|国巨|村田; Part Name: 贴片电容; Part Number: C020102120066; Price: 0.02
C74 = C-0402: DSC1: ±0.25PF; DSC2: 50V; DSC3: C0G; ERP Number: 1010200056; ID: 18; Manufacture: 三星|国巨|村田; Part Name: 贴片电容; Part Number: C020102120018; Price: 0.01
D20 D23 D24 D27 = DI-SC1206-150ASMD: DSC1: 150V; DSC2: ±30%; DSC3: 500A; DSC4: SMD,3.2x1.6mm; ID: 2; Manufacture: 硕凯; Part Name: 放电管; Part Number: C040702270002; Price: 0.4
D28 D29 = DI-ESD-SRV05-4: DSC1: 单向; DSC2: Vrwm=5V; DSC3: VBR=6V; DSC4: Vc=13V; DSC5: Ipp=3.5A; DSC6: Ppp=45W; DSC7: Cj=0.36pF; ERP Number: 1010800050; ID: 15; Manufacture: 伯恩半导体; Part Name: TVS; Part Number: C040602260015; Price: 0.21; Solder: 量产
J55 = J-RJ45-1X2: DSC1: RJ45网口连接器,带LED灯,8p8c,横向并排双座,黑色,后脚,4.57,铜壳,无弹片; DSC3: 通孔弯针; ID: 2; Part Number: J120103060002
R82 R84 R86 R88-R90 R92 R94 = R-0402: DSC1: ±1%; DSC2: 1/16W; ID: 453; Part Name: 贴片电阻; Part Number: C011002080453; Price: 0.01
R83 R87 R91 R93 = R-0603: DSC1: ±1%; DSC2: 1/10W; ERP Number: 1010200269; ID: 1,348; Part Name: 贴片电阻; Part Number: C011002081348; Price: 0.01
R95 = R-0805: DSC1: ±1%; DSC2: 1/8W; ERP Number: 1010200447; ID: 1,864; Part Name: 贴片电阻; Part Number: C011002081864; Price: 0.01
R110 = R-0402: DSC1: ±1%; DSC2: 1/16W; ERP Number: 1010200185; ID: 835; Part Name: 贴片电阻; Part Number: C011002080835; Price: 0.01
U11 = U-KSZ8081RNAIA-TR: DSC1: 10BASE-T/100BASE-TX Physical Layer ?Transceiver, RMII,IEEE 802.3; DSC2: QFN24，4mm×4mm，0.5mm Pitch; DSC3: -40℃~+85℃; ERP Number: 1010100248; ID: 3; Manufacture: MICROCHIP(美国微芯); Part Name: 以太网芯片; Part Number: C100102490003; Price: 5.3
U30 = U-QT24A01_0: DSC1: 贴片 单口千兆或双口百兆; DSC2: 0~70℃; DSC3: SMD,SOP24,15.1*7*4mm; ERP Number: C060702390002; ID: 2; Part Name: 网口变压器

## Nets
5V_SENSE_: M1.91(GPIO1_IO04)
GND: C34.1 C35.1 C36.1 C37.1 C38.1 C45.1 C46.1 C47.1 C48.1 C49.1 C50.1 C51.1 C52.1 C53.1 C54.1 C55.1 C57.1 C58.1 C59.2 C61.2 C63.2 C65.2 C66.1 C68.1 C69.1 C70.1 C71.1 C72.1 C73.1 C74.1 C187.1 C211.1 D16.2(I/O1) D17.2(I/O1) D18.2(I/O1) D19.2(I/O1) D28.2 D29.2 D96.1(I/O2) D113.2(I/O1) D114.2(I/O1) D115.2(I/O1) D116.2(I/O1) D117.2(I/O1) J7.4(GND1) M1.5(GND) M1.35(GND) M1.42(GND) M1.55(GND) M1.73(GND) M1.78(GND) M1.81(GND) M1.98(GND) M1.115(GND) M1.126(GND) R53.1 R55.1 R68.2 R69.2 R70.2 R76.2 R78.2 R79.2 R80.2 R81.2 R95.1 R109.2 R110.1 R313.2 R314.2 U7.2(GND) U8.11(TEST) U8.37(EPAD(VSS)) U11.22(GND) U11.25(PAD_GND) U32.2(GND) XT2.2 XT2.4 ; also on sheet 8 9 10 11 12
GND_EARTH: C60.1 C62.1 C64.1 C66.2 C188.1 D20.2 D23.2 D24.2 D27.2 J7.5(GND2) J7.6(GND3) J7.7(GND4) J55.FG1 J55.FG2 R95.2 ; also on sheet 11 12
VCC5V: C45.2 C211.2 L5.1 U7.5(IN) U32.5(IN) ; also on sheet 8 11 12
VCC_SOM_3V3: C37.2 C38.2 L7.2 M1.97(VSYS_3V3)
VDD_SNVS_3V3: L6.1 R43.1 ; also on sheet 12
VDDCR: C72.2 C73.2 U11.1(VDD_1.2)
4G_PWREN_IO: M1.57(SNVS_TAMPER1) ; also on sheet 12
4G_RST_IO: M1.58(SNVS_TAMPER2) ; also on sheet 9
BOOT_MODE0: D96.2(I/O1) M1.68(BOOT_MODE0) R53.2 SW2.2
BOOT_MODE1: M1.69(BOOT_MODE1) R55.2
BUZZER_PWM: M1.30(LCD_RESET) ; also on sheet 12
CAN1_RX: M1.108(UART3_RTS) ; also on sheet 11
CAN1_TX: M1.107(UART3_CTS) ; also on sheet 11
CLK1_N: M1.79(CLK1_N)
CLK1_P: M1.80(CLK1_P)
CSI_DATA00: M1.47(CSI_DATA00) R40.1
CSI_DATA00/UART5_TX/SPI2_SLK: R40.2 ; also on sheet 8
CSI_DATA01: M1.48(CSI_DATA01) R41.1
CSI_DATA01/UART5_RX/SPI2_SS0: R41.2 ; also on sheet 8
CSI_DATA02: M1.49(CSI_DATA02) R44.1
CSI_DATA02/UART5_RTS/SPI2_MOSI: R44.2 ; also on sheet 8
CSI_DATA03: M1.50(CSI_DATA03) R45.1
CSI_DATA03/UART5_RTS/SPI2_MISO: R45.2 ; also on sheet 8
CSI_DATA04: M1.51(CSI_DATA04) R46.1
CSI_DATA04/SPI1_SCLK: R46.2 ; also on sheet 8
CSI_DATA05: M1.52(CSI_DATA05) R47.1
CSI_DATA05/SPI1_SS0: R47.2 ; also on sheet 8
CSI_DATA06: M1.53(CSI_DATA06) R48.1
CSI_DATA06/SPI1_MOSI: R48.2 ; also on sheet 8
CSI_DATA07: M1.54(CSI_DATA07) R49.1
CSI_DATA07/SPI1_MISO: R49.2 ; also on sheet 8
CSI_HSYNC: M1.46(CSI_HSYNC) R52.1 ; also on sheet 8 10
CSI_HSYNC/I2C_SCL/UART6_CTS/PWM8: R52.2 ; also on sheet 8
CSI_MCLK: M1.43(CSI_MCLK) R50.1 ; also on sheet 8
CSI_MCLK/I2C1_SDA/UART6_TX: R50.2 ; also on sheet 8
CSI_PIXCLK: M1.44(CSI_PIXCLK) R51.1 ; also on sheet 8
CSI_PIXCLK/I2C1_SCL/UART6_RX: R51.2 ; also on sheet 8
CSI_VSYNC: M1.45(CSI_VSYNC) R54.1 ; also on sheet 8 10
CSI_VSYNC/I2C_SDA/UART6_RTS/PWM7: R54.2 ; also on sheet 8
DN0: D17.1(I/O2) J7.2(D-) L9.3
DN1: D19.1(I/O2) L10.4 ; also on sheet 8
DP0: D16.1(I/O2) J7.3(D+) L9.4
DP1: D18.1(I/O2) L10.3 ; also on sheet 8
ENET2_CRS_DV: M1.116(ENET2_CRS_DV) R107.1
ENET2_nRST: M1.88(GPIO1_IO09) R108.1
ENET2_RXD0: M1.119(ENET2_RXD0) R104.1
ENET2_RXD1: M1.118(ENET2_RXD1) R105.1
ENET2_RXER: M1.117(ENET2_RXER) R106.1
ENET2_TX_CLK: M1.120(ENET2_TX_CLK) R112.1
ENET2_TXD0: M1.123(ENET2_TXD0) R100.1
ENET2_TXD1: M1.122(ENET2_TXD1) R101.1
ENET2_TXEN: M1.121(ENET2_TXEN) R102.1
ENET_MDC: M1.124(ENET_MDC) R99.1
ENET_MDIO: M1.125(ENET_MDIO) R98.1
ETH1X_LED1: M1.128(ETH1X_LED1) R85.1
ETH1X_LED1N: D116.1(I/O2) J55.B9(BLEDY-) R85.2
ETH1X_RXN: M1.3(ETH1_RXN) R88.1
ETH1X_RXN_: D22.2(I/O1) D28.3 R88.2 U30.6(TD2-)
ETH1X_RXP: M1.4(ETH1_RXP) R86.1
ETH1X_RXP_: D22.1(I/O2) D28.4 R86.2 U30.5(TD2+)
ETH1X_TXN: M1.1(ETH1_TXN) R84.1
ETH1X_TXN_: D21.2(I/O1) D28.6 R84.2 U30.3(TD1-)
ETH1X_TXP: M1.2(ETH1_TXP) R82.1
ETH1X_TXP_: D21.1(I/O2) D28.1 R82.2 U30.2(TD1+)
ETH2X_AVDD: C69.2 C70.2 L11.2 U11.2(VDDA_3.3)
ETH2X_CRSDV: R107.2 R111.1 U11.15(CRS_DV/PHYAD)
ETH2X_LED2N: D117.1(I/O2) J55.A11(ALEDG-) R103.2
ETH2X_MDC: R99.2 U11.11(MDC)
ETH2X_MDIO: R98.2 U11.10(MDIO)
ETH2X_RSTB: R108.2 R109.1 U11.24(RST#)
ETH2X_RX0: R104.2 U11.13(RXD0)
ETH2X_RX1: R105.2 U11.12(RXD1)
ETH2X_RXER: R106.2 U11.17(RXER)
ETH2X_RXN: R94.1 U11.3(RXM)
ETH2X_RXN_: D26.2(I/O1) D29.3 R94.2 U30.12(TD4-)
ETH2X_RXP: R92.1 U11.4(RXP)
ETH2X_RXP_: D26.1(I/O2) D29.4 R92.2 U30.11(TD4+)
ETH2X_TX0: R100.2 U11.20(TXD0)
ETH2X_TX1: R101.2 U11.21(TXD1)
ETH2X_TXCK: C74.2 R112.2 U11.8(XI)
ETH2X_TXEN: R102.2 U11.19(TXEN)
ETH2X_TXN: R90.1 U11.5(TXM)
ETH2X_TXN_: D25.2(I/O1) D29.6 R90.2 U30.9(TD3-)
ETH2X_TXP: R89.1 U11.6(TXP)
ETH2X_TXP_: D25.1(I/O2) D29.1 R89.2 U30.8(TD3+)
GPIO1_IO00: M1.95(GPIO1_IO00) R68.1
GPIO1_IO01: M1.94(GPIO1_IO01) ; also on sheet 8
GPIO1_IO02: M1.93(GPIO1_IO02) ; also on sheet 8
GPIO1_IO03: M1.92(GPIO1_IO03)
GPIO1_IO05: M1.90(GPIO1_IO05) R69.1 U7.4(EN)
GPIO1_IO08: M1.89(GPIO1_IO08) ; also on sheet 8
GPIO-DI: M1.62(SNVS_TAMPER6) ; also on sheet 11
GPIO_LCD_EN: M1.56(SNVS_TAMPER0) ; also on sheet 8
JTAG_MOD: M1.87(JTAG_MOD) ; also on sheet 11
JTAG_nTRST: M1.86(JTAG_nTRST)
JTAG_TCK: M1.82(JTAG_TCK)
JTAG_TDI: M1.84(JTAG_TDI)
JTAG_TDO: M1.85(JTAG_TDO)
JTAG_TMS: M1.83(JTAG_TMS)
LAN1-R+: J55.B3 U30.20(MX2+)
LAN1-R-: J55.B6 U30.19(MX2-)
LAN1-T+: J55.B1 U30.23(MX1+)
LAN1-T-: J55.B2 U30.22(MX1-)
LAN2-R+: J55.A3 U30.14(MX4+)
LAN2-R-: J55.A6 U30.13(MX4-)
LAN2-T+: J55.A1 U30.17(MX3+)
LAN2-T-: J55.A2 U30.16(MX3-)
LCD_DATA0: M1.29(LCD_DATA0) ; also on sheet 8
LCD_DATA1: M1.28(LCD_DATA1) ; also on sheet 8
LCD_DATA2: M1.27(LCD_DATA2) ; also on sheet 8
LCD_DATA3: M1.26(LCD_DATA3) ; also on sheet 8
LCD_DATA4: M1.25(LCD_DATA4) ; also on sheet 8
LCD_DATA5: M1.24(LCD_DATA5) ; also on sheet 8
LCD_DATA6: M1.23(LCD_DATA6) ; also on sheet 8
LCD_DATA7: M1.22(LCD_DATA7) ; also on sheet 8
LCD_DATA8: M1.21(LCD_DATA8) ; also on sheet 8
LCD_DATA9: M1.20(LCD_DATA9) ; also on sheet 8
LCD_DATA10: M1.19(LCD_DATA10) ; also on sheet 8
LCD_DATA11: M1.18(LCD_DATA11) ; also on sheet 8
LCD_DATA12: M1.17(LCD_DATA12) ; also on sheet 8
LCD_DATA13: M1.16(LCD_DATA13) ; also on sheet 8
LCD_DATA14: M1.15(LCD_DATA14) ; also on sheet 8
LCD_DATA15: M1.14(LCD_DATA15) ; also on sheet 8
LCD_DATA16: M1.13(LCD_DATA16) ; also on sheet 8
LCD_DATA17: M1.12(LCD_DATA17) ; also on sheet 8
LCD_DATA18: M1.11(LCD_DATA18) R32.1
LCD_DATA19: M1.10(LCD_DATA19) R33.1
LCD_DATA20: M1.9(LCD_DATA20) R34.1
LCD_DATA21: M1.8(LCD_DATA21) R35.1
LCD_DATA22: M1.7(LCD_DATA22) R36.1
LCD_DATA23: M1.6(LCD_DATA23) R37.1
LCD_DE: M1.34(LCD_DE) ; also on sheet 8
LCD_HSYNC: M1.32(LCD_HSYNC) ; also on sheet 8
LCD_PCLK: M1.33(LCD_PCLK) ; also on sheet 8
LCD_VSYNC: M1.31(LCD_VSYNC) ; also on sheet 8
ONOFF: M1.70(ONOFF)
PMIC_ON_REQ: M1.66(PMIC_ON_REQ) ; also on sheet 12
PMIC_STBY_REQ: M1.67(PMIC_STBY_REQ)
POR_B: M1.127(POR_B) R75.1
RS485_EN_1: M1.99(UART1_CTS) ; also on sheet 11
SD1_CLK: M1.36(SD1_CLK) ; also on sheet 10
SD1_CMD: M1.37(SD1_CMD) ; also on sheet 10
SD1_DATA0: M1.41(SD1_DATA0) ; also on sheet 10
SD1_DATA1: M1.40(SD1_DATA1) ; also on sheet 10
SD1_DATA2: M1.39(SD1_DATA2) ; also on sheet 10
SD1_DATA3: M1.38(SD1_DATA3) ; also on sheet 10
SD2_CLK/PWM6: R33.2 ; also on sheet 8
SD2_CMD/PWM5: R32.2 ; also on sheet 8
SD2_D0/UART8_TX/SPI1_SCLK: R34.2 ; also on sheet 8
SD2_D1/UART8_RX/SPI1_SS0: R35.2 ; also on sheet 8
SD2_D2/SPI1_MOSI: R36.2 ; also on sheet 8
SD2_D3/SPI1_MISO: R37.2 ; also on sheet 8
SNVS_TAMPER3: M1.59(SNVS_TAMPER3) R339.1
SNVS_TAMPER4: M1.60(SNVS_TAMPER4) R338.1
SNVS_TAMPER5: M1.61(SNVS_TAMPER5) ; also on sheet 12
SNVS_TAMPER7: M1.63(SNVS_TAMPER7) ; also on sheet 12
SNVS_TAMPER8: M1.64(SNVS_TAMPER8) R313.1 U32.4(EN)
SNVS_TAMPER9: M1.65(SNVS_TAMPER9) ; also on sheet 9
SYS_3V3: C47.2 C49.2 C50.2 C51.2 C52.2 C53.2 C68.2 C71.2 J55.A10(ALEDY+) J55.A12(ALEDG+) J55.B10(BLEDY+) J55.B12(BLEDG+) L7.1 L11.1 R71.1 R111.2 R239.1 U8.5(VDDA33_1) U8.10(VDDA33_2) U8.15(VDD33(REG)) U8.23(VDD33(IO)) U8.29(VDDA33_3) U8.36(VDDA33_4) U11.14(VDDIO) ; also on sheet 8 9 10 11 12
UART1_RTS: M1.100(UART1_RTS) ; also on sheet 10
UART1_RX_DATA: M1.101(UART1_RX_DATA) ; also on sheet 11
UART1_TX_DATA: M1.102(UART1_TX_DATA) ; also on sheet 11
UART2_CTS: M1.103(UART2_CTS) R38.1
UART2_CTS/CAN2_TX: R38.2 ; also on sheet 8
UART2_RTS: M1.104(UART2_RTS) R39.1
UART2_RTS/CAN2_RX: R39.2 ; also on sheet 8
UART2_RX_DATA: M1.105(UART2_RX_DATA) ; also on sheet 8
UART2_TX_DATA: M1.106(UART2_TX_DATA) ; also on sheet 8
UART3_RX_DATA: M1.109(UART3_RX_DATA) ; also on sheet 11
UART3_TX_DATA: M1.110(UART3_TX_DATA) ; also on sheet 11
UART4_RX_DATA: M1.111(UART4_RX_DATA) ; also on sheet 11
UART4_TX_DATA: M1.112(UART4_TX_DATA) ; also on sheet 11
UART5_RX_DATA: M1.114(UART5_RX_DATA) ; also on sheet 11
UART5_TX_DATA: M1.113(UART5_TX_DATA) ; also on sheet 11
USB_5V: C55.2 U32.1(VOUT) ; also on sheet 8
USB_A0_DN: R73.1 U8.30(USBDM_UP)
USB_A0_DP: R72.1 U8.31(USBDP_UP)
USB_A1_DN: L10.1 U8.1(USBDM_DN1/PRT_DIS_M1)
USB_A1_DP: L10.2 U8.2(USBDP_DN1/PRT_DIS_P1)
USB_A2_DN: U8.3(USBDM_DN2/PRT_DIS_M2) ; also on sheet 8
USB_A2_DP: U8.4(USBDP_DN2/PRT_DIS_P2) ; also on sheet 8
USB_A3_DN: U8.6(USBDM_DN3/PRT_DIS_M3) ; also on sheet 9
USB_A3_DP: U8.7(USBDP_DN3/PRT_DIS_P3) ; also on sheet 9
USB_A4_DN: U8.8(USBDM_DN4/PRT_DIS_M4) ; also on sheet 9
USB_A4_DP: U8.9(USBDP_DN4/PRT_DIS_P4) ; also on sheet 9
USB_OTG1_DN: L9.2 M1.75(USB_OTG1_DN)
USB_OTG1_DP: L9.1 M1.74(USB_OTG1_DP)
USB_OTG1_VBUS: C34.2 C46.2 D115.1(I/O2) J7.1(VBUS) M1.77(USB_OTG1_VBUS) U7.1(VOUT)
USB_OTG2_DN: M1.71(USB_OTG2_DN) R73.2
USB_OTG2_DP: M1.72(USB_OTG2_DP) R72.2
USB_OTG2_VBUS: C35.2 L5.2 M1.76(USB_OTG2_VBUS)
USR_LED0: D113.1(I/O2) J55.B11(BLEDG-) R339.2
USR_LED1: D114.1(I/O2) J55.A9(ALEDY-) R338.2
VSNVS_IN: C36.2 L6.2 M1.96(VSNVS)
N20607: R70.1 U7.3(OCB)
N64378: R43.2 SW2.1
N210629: D23.1 R87.1 U30.21(MCT2)
N210642: D20.1 R83.1 U30.24(MCT1)
N211934: D27.1 R93.1 U30.15(MCT4)
N211946: D24.1 R91.1 U30.18(MCT3)
N213480: J55.A4 J55.A5
N213493: J55.B4 J55.B5
N213506: J55.A7 J55.A8
N213521: J55.B7 J55.B8
N216739: R110.2 U11.9(REXT)
N217207: R103.1 U11.23(LED0/ANEN_SPEED)
N232482: R71.2 U8.27(VBUS_DET)
N232774: R78.1 U8.22(SDA/SMBDATA/NON_REM1)
N232778: R79.1 U8.24(SCL/SMBCLK/CFG_SEL0)
N232782: R80.1 U8.25(HS_IND/CFG_SEL1)
N232839: R81.1 U8.28(SUSP_IND/LOCAL_PWR/NON_REM0)
N232976: R76.1 U8.35(RBIAS)
N241974: C57.2 R77.1 U8.33(XTALIN/CLKIN) XT2.3
N241984: C58.2 R77.2 U8.32(XTALOUT) XT2.1
N243129: C187.2 R75.2 R239.2 U8.26(RESET_N)
N244208: C48.2 U8.34(PLLFILT)
N244212: C54.2 U8.14(CRFILT)
N685174: C59.1 U30.1(TCT1)
N685178: C61.1 U30.4(TCT2)
N685448: C63.1 U30.7(TCT3)
N685452: C65.1 U30.10(TCT4)
N686070: C62.2 R87.2
N686102: C60.2 R83.2
N686407: C64.2 R91.2
N686411: C188.2 R93.2
N897515: R314.1 U32.3(OCB)

Not connected (* = marked no-connect by the designer): D28 5*; D29 5*; J55 NC1* NC2*; SW2 3 4; U8 12(PRTPWR1/BC_EN1)* 13(OCS_N1)* 16(PRTPWR2/BC_EN2)* 17(OCS_N2)* 18(PRTPWR3/BC_EN3)* 19(OCS_N3)* 20(PRTPWR4/BC_EN4)* 21(OCS_N4)*; U11 7(XO)* 16(REF_CLK)* 18(INTRP)*

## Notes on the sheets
sheet 1
- NOTE:
- All pins using ~reset as harden :
- PAD
- Default State
- Simulation Value
- UART3_TX_DATA
- Output Buffer(LOW) during reset --> Output keeper + Input enable after reset done
- 0 in real silicon
- LCD_DATA00~LCD_DATA23
- 100K pull down + input enable during reset --> Output keeper + Input enable
  after reset done ( this is boot option, we don’t need change)
- 0 in real silicon
- PAD
- Default State
- Signal Path
- PAD Simulation Value
- UART3_TX_DATA
- Output Buffer(LOW) during reset --> Output keeper + Input enable after reset done
- sjc.ipt_jta_active --> PAD
- 0 in real silicon
- (note : sjc.ipt_jta_active
  also connected to
  snvs_hp.sec_vio_in_1.
  This is security related,
  we don’t plan to change
  it.)
- ALT7
- All pins using ~src.en_system_clk as harden :
- PAD
- Default State
- Simulation Value
- GPIO1_IO03
- 100K pull down + input enable during reset --> Output keeper + Input enable
  after reset done
- 0 in real silicon
- PAD
- Default State
- Signal Path
- PAD Simulation Value
- GPIO1_IO03
- 100K pull down + input enable during reset --> Output keeper + Input enable after
  reset done
- PAD --> ccmsrcmix. src_tester_ack
- 0 in real silicon
- This is the requirement of TE test
- ALT7
- All pins using snvs_hp.snvs_sec_vio_in_5_en as harden :
- PAD
- Default State
- Simulation Value
- CSI_PIXCLK
- Output keeper + Input enable (snvs_sec_vio_in_5_en is 1’b0 in normal state, so
  harden is not triggerd in normal state). snvs_sec_vio_in_5_en is controlled by
  SNVS register. It can be disable or enable.
- X (0 or 1 in real silicon )
sheet 2
- i.MX6ULL IOMUX
- NAME
- Default
- ALT0
- ALT1
- ALT2
- ALT3
- ALT4
- ALT5
- ALT6
- ALT7
- ALT8
- ALT9
- PAD DFU
- TEST_MODE
  POR_B
  ONOFF
  SNVS_PMIC_ON_REQ
  CCM_PMIC_STBY_REQ
  BOOT_MODE0
  BOOT_MODE1
  SNVS_TAMPER0
  SNVS_TAMPER1
  SNVS_TAMPER2
  SNVS_TAMPER3
  SNVS_TAMPER4
  SNVS_TAMPER5
  SNVS_TAMPER6
  SNVS_TAMPER7
  SNVS_TAMPER8
  SNVS_TAMPER9
  JTAG_MOD
  JTAG_TMS
  JTAG_TDO
  JTAG_TDI
  JTAG_TCK
  JTAG_TRST_B
  GPIO1_IO00
  GPIO1_IO01
  GPIO1_IO02
  GPIO1_IO03
  GPIO1_IO04
  GPIO1_IO05
  GPIO1_IO06
  GPIO1_IO07
  GPIO1_IO08
  GPIO1_IO09
  UART1_TXD
  UART1_RXD
  UART1_CTS
  UART1_RTS
  UART2_TXD
  UART2_RXD
  UART2_CTS
  UART2_RTS
  UART3_TXD
  UART3_RXD
  UART3_CTS
  UART3_RTS
  UART4_TXD
  UART4_RXD
  UART5_TXD
  UART5_RXD
  ENET1_RXD0
  ENET1_RXD1
  ENET1_CRS_DV
  ENET1_TXD0
  ENET1_TXD1
  ENET1_TXEN
  ENET1_TXCLK
  ENET1_RXER
  ENET2_RXD0
  ENET2_RXD1
  ENET2_CRS_DV
  ENET2_TXD0
  ENET2_TXD1
  ENET2_TXEN
  ENET2_TXCLK
  ENET2_RXER
  LCD_CLK
  LCD_ENABLE
  LCD_HSYNC
  LCD_VSYNC
  LCD_RESET
  LCD_DATA00
  LCD_DATA01
  LCD_DATA02
  LCD_DATA03
  LCD_DATA04
  LCD_DATA05
  LCD_DATA06
  LCD_DATA07
  LCD_DATA08
  LCD_DATA09
  LCD_DATA10
  LCD_DATA11
  LCD_DATA12
  LCD_DATA13
  LCD_DATA14
  LCD_DATA15
  LCD_DATA16
  LCD_DATA17
  LCD_DATA18
  LCD_DATA19
  LCD_DATA20
  LCD_DATA21
  LCD_DATA22
  LCD_DATA23
  NAND_RE_B
  NAND_WE_B
  NAND_DATA00
  NAND_DATA01
  NAND_DATA02
  NAND_DATA03
  NAND_DATA04
  NAND_DATA05
  NAND_DATA06
  NAND_DATA07
  NAND_ALE
  NAND_WP_B
  NAND_READY_B
  NAND_CE0_B
  NAND_CE1_B
  NAND_CLE
  NAND_DQS
  SD1_CMD
  SD1_CLK
  SD1_DATA0
  SD1_DATA1
  SD1_DATA2
  SD1_DATA3
  CSI_MCLK
  CSI_PIXCLK
  CSI_VSYNC
  CSI_HSYNC
  CSI_DATA00
  CSI_DATA01
  CSI_DATA02
  CSI_DATA03
  CSI_DATA04
  CSI_DATA05
  CSI_DATA06
  CSI_DATA07
- tcu.TEST_MODE
  src.POR_B
  src.RESET_B
  snvs_lp_wrapper.SNVS_WAKEUP_ALARM
  ccm.PMIC_VSTBY_REQ
  src.BOOT_MODE[0]
  src.BOOT_MODE[1]
  snvs_lp_wrapper.SNVS_TD1
  snvs_lp_wrapper.SNVS_TD1
  snvs_lp_wrapper.SNVS_TD1
  snvs_lp_wrapper.SNVS_TD1
  snvs_lp_wrapper.SNVS_TD1
  snvs_lp_wrapper.SNVS_TD1
  snvs_lp_wrapper.SNVS_TD1
  snvs_lp_wrapper.SNVS_TD1
  snvs_lp_wrapper.SNVS_TD1
  snvs_lp_wrapper.SNVS_TD1
  sjc.MOD
  sjc.TMS
  sjc.TDO
  sjc.TDI
  sjc.TCK
  sjc.TRSTB
  gpio1.IO[0]
  gpio1.IO[1]
  gpio1.IO[2]
  gpio1.IO[3]
  gpio1.IO[4]
  gpio1.IO[5]
  gpio1.IO[6]
  gpio1.IO[7]
  gpio1.IO[8]
  gpio1.IO[9]
  gpio1.IO[16]
  gpio1.IO[17]
  gpio1.IO[18]
  gpio1.IO[19]
  gpio1.IO[20]
  gpio1.IO[21]
  gpio1.IO[22]
  gpio1.IO[23]
  gpio1.IO[24]
  gpio1.IO[25]
  gpio1.IO[26]
  gpio1.IO[27]
  gpio1.IO[28]
  gpio1.IO[29]
  gpio1.IO[30]
  gpio1.IO[31]
  gpio2.IO[0]
  gpio2.IO[1]
  gpio2.IO[2]
  gpio2.IO[3]
  gpio2.IO[4]
  gpio2.IO[5]
  gpio2.IO[6]
  gpio2.IO[7]
  gpio2.IO[8]
  gpio2.IO[9]
  gpio2.IO[10]
  gpio2.IO[11]
  gpio2.IO[12]
  gpio2.IO[13]
  gpio2.IO[14]
  gpio2.IO[15]
  gpio3.IO[0]
  gpio3.IO[1]
  gpio3.IO[2]
  gpio3.IO[3]
  gpio3.IO[4]
  gpio3.IO[5]
  gpio3.IO[6]
  gpio3.IO[7]
  gpio3.IO[8]
  gpio3.IO[9]
  gpio3.IO[10]
  gpio3.IO[11]
  gpio3.IO[12]
  gpio3.IO[13]
  gpio3.IO[14]
  gpio3.IO[15]
  gpio3.IO[16]
  gpio3.IO[17]
  gpio3.IO[18]
  gpio3.IO[19]
  gpio3.IO[20]
  gpio3.IO[21]
  gpio3.IO[22]
  gpio3.IO[23]
  gpio3.IO[24]
  gpio3.IO[25]
  gpio3.IO[26]
  gpio3.IO[27]
  gpio3.IO[28]
  gpio4.IO[0]
  gpio4.IO[1]
  gpio4.IO[2]
  gpio4.IO[3]
  gpio4.IO[4]
  gpio4.IO[5]
  gpio4.IO[6]
  gpio4.IO[7]
  gpio4.IO[8]
  gpio4.IO[9]
  gpio4.IO[10]
  gpio4.IO[11]
  gpio4.IO[12]
  gpio4.IO[13]
  gpio4.IO[14]
  gpio4.IO[15]
  gpio4.IO[16]
  gpio2.IO[16]
  gpio2.IO[17]
  gpio2.IO[18]
  gpio2.IO[19]
  gpio2.IO[20]
  gpio2.IO[21]
  gpio4.IO[17]
  gpio4.IO[18]
  gpio4.IO[19]
  gpio4.IO[20]
  gpio4.IO[21]
  gpio4.IO[22]
  gpio4.IO[23]
  gpio4.IO[24]
  gpio4.IO[25]
  gpio4.IO[26]
  gpio4.IO[27]
  gpio4.IO[28]
- tcu.TEST_MODE
  src.POR_B
  src.RESET_B
  snvs_lp_wrapper.PMIC_ON_REQ
  ccm.PMIC_VSTBY_REQ
  src.BOOT_MODE[0]
  src.BOOT_MODE[1]
  snvs_lp_wrapper.TAMPER[0]
  snvs_lp_wrapper.TAMPER[1]
  snvs_lp_wrapper.TAMPER[2]
  snvs_lp_wrapper.TAMPER[3]
  snvs_lp_wrapper.TAMPER[4]
  snvs_lp_wrapper.TAMPER[5]
  snvs_lp_wrapper.TAMPER[6]
  snvs_lp_wrapper.TAMPER[7]
  snvs_lp_wrapper.TAMPER[8]
  snvs_lp_wrapper.TAMPER[9]
  sjc.MOD
  sjc.TMS
  sjc.TDO
  sjc.TDI
  sjc.TCK
  sjc.TRSTB
  i2c2.SCL
  i2c2.SDA
  i2c1.SCL
  i2c1.SDA
  anatop.ENET_REF_CLK1
  anatop.ENET_REF_CLK2
  enet1.MDIO
  enet1.MDC
  pwm1.OUT
  pwm2.OUT
  uart1.TX
  uart1.RX
  uart1.CTS_B
  uart1.RTS_B
  uart2.TX
  uart2.RX
  uart2.CTS_B
  uart2.RTS_B
  uart3.TX
  uart3.RX
  uart3.CTS_B
  uart3.RTS_B
  uart4.TX
  uart4.RX
  uart5.TX
  uart5.RX
  enet1.RDATA[0]
  enet1.RDATA[1]
  enet1.RX_EN
  enet1.TDATA[0]
  enet1.TDATA[1]
  enet1.TX_EN
  enet1.TX_CLK
  enet1.RX_ER
  enet2.RDATA[0]
  enet2.RDATA[1]
  enet2.RX_EN
  enet2.TDATA[0]
  enet2.TDATA[1]
  enet2.TX_EN
  enet2.TX_CLK
  enet2.RX_ER
  lcdif.CLK
  lcdif.ENABLE
  lcdif.HSYNC
  lcdif.VSYNC
  lcdif.RESET
  lcdif.DATA[0]
  lcdif.DATA[1]
  lcdif.DATA[2]
  lcdif.DATA[3]
  lcdif.DATA[4]
  lcdif.DATA[5]
  lcdif.DATA[6]
  lcdif.DATA[7]
  lcdif.DATA[8]
  lcdif.DATA[9]
  lcdif.DATA[10]
  lcdif.DATA[11]
  lcdif.DATA[12]
  lcdif.DATA[13]
  lcdif.DATA[14]
  lcdif.DATA[15]
  lcdif.DATA[16]
  lcdif.DATA[17]
  lcdif.DATA[18]
  lcdif.DATA[19]
  lcdif.DATA[20]
  lcdif.DATA[21]
  lcdif.DATA[22]
  lcdif.DATA[23]
  rawnand.RE_B
  rawnand.WE_B
  rawnand.DATA00
  rawnand.DATA01
  rawnand.DATA02
  rawnand.DATA03
  rawnand.DATA04
  rawnand.DATA05
  rawnand.DATA06
  rawnand.DATA07
  rawnand.ALE
  rawnand.WP_B
  rawnand.READY_B
  rawnand.CE0_B
  rawnand.CE1_B
  rawnand.CLE
  rawnand.DQS
  usdhc1.CMD
  usdhc1.CLK
  usdhc1.DATA0
  usdhc1.DATA1
  usdhc1.DATA2
  usdhc1.DATA3
  csi.MCLK
  csi.PIXCLK
  csi.VSYNC
  csi.HSYNC
  csi.DATA[2]
  csi.DATA[3]
  csi.DATA[4]
  csi.DATA[5]
  csi.DATA[6]
  csi.DATA[7]
  csi.DATA[8]
  csi.DATA[9]
- gpt2.CLK
  gpt2.CAPTURE1
  gpt2.CAPTURE2
  gpt2.COMPARE1
  gpt2.COMPARE2
  gpt2.COMPARE3
  gpt1.CAPTURE1
  gpt1.COMPARE1
  gpt1.COMPARE2
  gpt1.COMPARE3
  pwm3.OUT
  pwm4.OUT
  enet2.MDIO
  enet2.MDC
  wdog1.WDOG_B
  global wdog
  enet1.RDATA[2]
  enet1.RDATA[3]
  enet1.RX_CLK
  enet1.TX_ER
  enet1.TDATA[2]
  enet1.TDATA[3]
  enet1.CRS
  enet1.COL
  enet2.RDATA[2]
  enet2.RDATA[3]
  enet2.RX_CLK
  enet2.TX_ER
  enet2.TDATA[2]
  enet2.TDATA[3]
  enet2.CRS
  enet2.COL
  uart4.RTS_B
  uart4.CTS_B
  uart5.RTS_B
  uart5.CTS_B
  uart6.CTS_B
  uart6.RTS_B
  uart7.CTS_B
  uart7.RTS_B
  uart6.TX
  uart6.RX
  uart7.TX
  uart7.RX
  uart8.TX
  uart8.RX
  uart8.CTS_B
  uart8.RTS_B
  lcdif.WR_RWN
  lcdif.RD_E
  lcdif.RS
  lcdif.BUSY
  lcdif.CS
  pwm1.OUT
  pwm2.OUT
  pwm3.OUT
  pwm4.OUT
  uart8.CTS_B
  uart8.RTS_B
  uart7.CTS_B
  uart7.RTS_B
  spdif.IN
  sai3.MCLK
  sai3.RX_SYNC
  sai3.RX_BCLK
  sai3.TX_SYNC
  sai3.TX_BCLK
  sai3.RX_DATA
  sai3.TX_DATA
  uart7.TX
  uart7.RX
  pwm5.OUT
  pwm6.OUT
  uart8.TX
  uart8.RX
  mqs.RIGHT
  mqs.LEFT
  usdhc2.CLK
  usdhc2.CMD
  usdhc2.DATA0
  usdhc2.DATA1
  usdhc2.DATA2
  usdhc2.DATA3
  usdhc2.DATA4
  usdhc2.DATA5
  usdhc2.DATA6
  usdhc2.DATA7
  usdhc2.RESET_B
  usdhc1.RESET_B
  usdhc1.DATA4
  usdhc1.DATA5
  usdhc1.DATA6
  usdhc1.DATA7
  csi.FIELD
  gpt2.COMPARE1
  gpt2.COMPARE2
  gpt2.COMPARE3
  gpt2.CLK
  gpt2.CAPTURE1
  gpt2.CAPTURE2
  usdhc2.CD_B
  usdhc2.WP
  usdhc2.CLK
  usdhc2.CMD
  usdhc2.DATA0
  usdhc2.DATA1
  usdhc2.DATA2
  usdhc2.DATA3
  usdhc2.DATA4
  usdhc2.DATA5
  usdhc2.DATA6
  usdhc2.DATA7
- spdif.OUT
  sai2.MCLK
  sai2.TX_SYNC
  sai2.TX_BCLK
  sai2.RX_DATA
  sai2.TX_DATA
  anatop.OTG1_ID
  usb.OTG1_OC
  usb.OTG2_PWR
  usb.OTG2_OC
  usb.OTG1_PWR
  anatop.OTG2_ID
  usb.OTG_PWR_WAKE
  usb.OTG_HOST_MODE
  spdif.OUT
  spdif.IN
  i2c3.SCL
  i2c3.SDA
  usdhc1.WP
  usdhc1.CD_B
  i2c4.SCL
  i2c4.SDA
  can2.TX
  can2.RX
  can1.TX
  can1.RX
  i2c1.SCL
  i2c1.SDA
  i2c2.SCL
  i2c2.SDA
  pwm1.OUT
  pwm2.OUT
  osc32k.32K_OUT
  anatop.24M_OUT
  pwm5.OUT
  pwm6.OUT
  pwm7.OUT
  pwm8.OUT
  uart4.TX
  uart4.RX
  uart4.CTS_B
  uart4.RTS_B
  ca7_platform.EVENTI
  ca7_platform.TRACE[0]
  ca7_platform.TRACE[1]
  ca7_platform.TRACE[2]
  ca7_platform.TRACE[3]
  ca7_platform.TRACE[4]
  ca7_platform.TRACE[5]
  ca7_platform.TRACE[6]
  ca7_platform.TRACE[7]
  ca7_platform.TRACE[8]
  ca7_platform.TRACE[9]
  ca7_platform.TRACE[10]
  ca7_platform.TRACE[11]
  ca7_platform.TRACE[12]
  ca7_platform.TRACE[13]
  ca7_platform.TRACE[14]
  ca7_platform.TRACE[15]
  ca7_platform.TRACE_CLK
  ca7_platform.TRACE_CTL
  ca7_platform.EVENTO
  global wdog
  ecspi1.SCLK
  ecspi1.SS0
  ecspi1.MOSI
  ecspi1.MISO
  qspiB_SCLK
  qspiB_SS0_B
  qspiB_SS1_B
  qspiB_DQS
  qspiB_DATA[0]
  qspiB_DATA[1]
  qspiB_DATA[2]
  qspiB_DATA[3]
  sai2.RX_BCLK
  qspiA_SS1_B
  qspiA_DQS
  qspiA_SCLK
  qspiA_DATA[0]
  qspiA_DATA[1]
  qspiA_DATA[2]
  qspiA_DATA[3]
  qspiA_SS0_B
  sai2.RX_SYNC
  sai2.MCLK
  sai2.TX_SYNC
  sai2.TX_BCLK
  sai2.RX_DATA
  sai2.TX_DATA
  rawnand.CE2_B
  rawnand.CE3_B
- anatop.ENET_REF_CLK_25M
  ccm.CLKO1
  ccm.CLKO2
  ccm.OUT0
  ccm.OUT1
  ccm.OUT2
  anatop.ENET_REF_CLK1
  anatop.ENET_REF_CLK2
  anatop.ENET_REF_CLK_25M
  osc32k.32K_OUT
  anatop.24M_OUT
  csi.FIELD
  csi.MCLK
  csi.PIXCLK
  csi.VSYNC
  csi.HSYNC
  csi.DATA[2]
  csi.DATA[3]
  csi.DATA[4]
  csi.DATA[5]
  csi.DATA[6]
  csi.DATA[7]
  csi.DATA[8]
  csi.DATA[9]
  csi.DATA[1]
  csi.DATA[0]
  csi.DATA[10]
  csi.DATA[11]
  csi.DATA[12]
  csi.DATA[13]
  csi.DATA[14]
  csi.DATA[15]
  csi.DATA[16]
  csi.DATA[17]
  csi.DATA[18]
  csi.DATA[19]
  csi.DATA[20]
  csi.DATA[21]
  csi.DATA[22]
  csi.DATA[23]
  i2c3.SCL
  i2c3.SDA
  i2c4.SCL
  i2c4.SDA
  ecspi4.SCLK
  ecspi4.MOSI
  ecspi4.MISO
  ecspi4.SS0
  sai3.MCLK
  sai3.TX_SYNC
  sai3.TX_BCLK
  sai3.RX_DATA
  sai3.TX_DATA
  enet1.1588_EVENT2_IN
  enet1.1588_EVENT2_OUT
  enet1.1588_EVENT3_IN
  enet1.1588_EVENT3_OUT
  enet2.1588_EVENT2_IN
  enet2.1588_EVENT2_OUT
  enet2.1588_EVENT3_IN
  enet2.1588_EVENT3_OUT
  csi.DATA[16]
  csi.DATA[17]
  csi.DATA[18]
  csi.DATA[19]
  csi.DATA[20]
  csi.DATA[21]
  csi.DATA[22]
  csi.DATA[23]
  csi.DATA[1]
  csi.DATA[0]
  csi.DATA[10]
  csi.DATA[11]
  csi.DATA[12]
  csi.DATA[13]
  csi.DATA[14]
  csi.DATA[15]
  kpp.ROW[0]
  kpp.COL[0]
  kpp.ROW[1]
  kpp.COL[1]
  kpp.ROW[2]
  kpp.COL[2]
  ecspi4.SCLK
  ecspi4.MOSI
  ecspi4.MISO
  ecspi4.SS0
  pwm3.OUT
  pwm4.OUT
  ecspi3.SS0
  ecspi3.SCLK
  ecspi3.MOSI
  ecspi3.MISO
  pwm5.OUT
  spdif.OUT
  spdif.IN
  can1.TX
  can1.RX
  can2.TX
  can2.RX
  i2c1.SDA
  i2c1.SCL
  i2c2.SDA
  i2c2.SCL
  ecspi2.SCLK
  ecspi2.SS0
  ecspi2.MOSI
  ecspi2.MISO
  ecspi1.SCLK
  ecspi1.SS0
  ecspi1.MOSI
  ecspi1.MISO
- ccm.PMIC_RDY
  ccm.WAIT
  ccm.STOP
  pwm6.OUT
  pwm7.OUT
  pwm8.OUT
  mqs.RIGHT
  mqs.LEFT
  usdhc1.WP
  usdhc1.CD_B
  usdhc1.RESET_B
  usdhc1.VSELECT
  usdhc2.WP
  usdhc2.CD_B
  usdhc2.VSELECT
  usdhc2.RESET_B
  gpt1.COMPARE1
  gpt1.CLK
  enet2.1588_EVENT1_IN
  enet2.1588_EVENT1_OUT
  gpt1.CAPTURE1
  gpt1.CAPTURE2
  gpt1.COMPARE2
  gpt1.COMPARE3
  uart2.CTS_B
  uart2.RTS_B
  enet1.1588_EVENT1_IN
  enet1.1588_EVENT1_OUT
  csu.CSU_ALARM_AUT[2]
  csu.CSU_ALARM_AUT[1]
  csu.CSU_ALARM_AUT[0]
  csu.CSU_INT_DEB
  can1.TX
  can1.RX
  can2.TX
  can2.RX
  enet2.MDIO
  enet2.MDC
  anatop.ENET_REF_CLK1
  weim.CRE
  enet1.MDIO
  enet1.MDC
  weim.ADDR[26]
  weim.EB_B[2]
  weim.EB_B[3]
  weim.ACLK_FREERUN
  anatop.ENET_REF_CLK2
  weim.ADDR[25]
  weim.CS2_B
  weim.CS3_B
  wdog3.WDOG_RST_B_DEB
  wdog2.WDOG_B
  global wdog
  i2c3.SDA
  i2c3.SCL
  i2c4.SDA
  i2c4.SCL
  spdif.SR_CLK
  spdif.OUT
  spdif.LOCK
  spdif.EXT_CLK
  weim.DATA[0]
  weim.DATA[1]
  weim.DATA[2]
  weim.DATA[3]
  weim.DATA[4]
  weim.DATA[5]
  weim.DATA[6]
  weim.DATA[7]
  weim.DATA[8]
  weim.DATA[9]
  weim.DATA[10]
  weim.DATA[11]
  weim.DATA[12]
  weim.DATA[13]
  weim.DATA[14]
  weim.DATA[15]
  weim.EB_B[0]
  weim.EB_B[1]
  weim.AD[8]
  weim.AD[9]
  weim.AD[10]
  weim.AD[11]
  weim.AD[12]
  weim.AD[13]
  weim.AD[14]
  weim.AD[15]
  weim.ADDR[17]
  weim.BCLK
  weim.CS1_B
  weim.DTACK_B
  weim.ADDR[18]
  weim.ADDR[16]
  weim.WAIT
  weim.ADDR[19]
  weim.ADDR[20]
  weim.ADDR[21]
  weim.ADDR[22]
  weim.ADDR[23]
  weim.ADDR[24]
  weim.CS0_B
  weim.OE
  weim.RW
  weim.LBA_B
  weim.AD[0]
  weim.AD[1]
  weim.AD[2]
  weim.AD[3]
  weim.AD[4]
  weim.AD[5]
  weim.AD[6]
  weim.AD[7]
- gpio5.IO[10]
  gpio5.IO[11]
  gpio5.IO[0]
  gpio5.IO[1]
  gpio5.IO[2]
  gpio5.IO[3]
  gpio5.IO[4]
  gpio5.IO[5]
  gpio5.IO[6]
  gpio5.IO[7]
  gpio5.IO[8]
  gpio5.IO[9]
  gpio1.IO[10]
  gpio1.IO[11]
  gpio1.IO[12]
  gpio1.IO[13]
  gpio1.IO[14]
  gpio1.IO[15]
  gpio1.IO[0]
  gpio1.IO[1]
  gpio1.IO[2]
  gpio1.IO[3]
  gpio1.IO[4]
  gpio1.IO[5]
  gpio1.IO[6]
  gpio1.IO[7]
  gpio1.IO[8]
  gpio1.IO[9]
  gpio1.IO[16]
  gpio1.IO[17]
  gpio1.IO[18]
  gpio1.IO[19]
  gpio1.IO[20]
  gpio1.IO[21]
  gpio1.IO[22]
  gpio1.IO[23]
  gpio1.IO[24]
  gpio1.IO[25]
  gpio1.IO[26]
  gpio1.IO[27]
  gpio1.IO[28]
  gpio1.IO[29]
  gpio1.IO[30]
  gpio1.IO[31]
  gpio2.IO[0]
  gpio2.IO[1]
  gpio2.IO[2]
  gpio2.IO[3]
  gpio2.IO[4]
  gpio2.IO[5]
  gpio2.IO[6]
  gpio2.IO[7]
  gpio2.IO[8]
  gpio2.IO[9]
  gpio2.IO[10]
  gpio2.IO[11]
  gpio2.IO[12]
  gpio2.IO[13]
  gpio2.IO[14]
  gpio2.IO[15]
  gpio3.IO[0]
  gpio3.IO[1]
  gpio3.IO[2]
  gpio3.IO[3]
  gpio3.IO[4]
  gpio3.IO[5]
  gpio3.IO[6]
  gpio3.IO[7]
  gpio3.IO[8]
  gpio3.IO[9]
  gpio3.IO[10]
  gpio3.IO[11]
  gpio3.IO[12]
  gpio3.IO[13]
  gpio3.IO[14]
  gpio3.IO[15]
  gpio3.IO[16]
  gpio3.IO[17]
  gpio3.IO[18]
  gpio3.IO[19]
  gpio3.IO[20]
  gpio3.IO[21]
  gpio3.IO[22]
  gpio3.IO[23]
  gpio3.IO[24]
  gpio3.IO[25]
  gpio3.IO[26]
  gpio3.IO[27]
  gpio3.IO[28]
  gpio4.IO[0]
  gpio4.IO[1]
  gpio4.IO[2]
  gpio4.IO[3]
  gpio4.IO[4]
  gpio4.IO[5]
  gpio4.IO[6]
  gpio4.IO[7]
  gpio4.IO[8]
  gpio4.IO[9]
  gpio4.IO[10]
  gpio4.IO[11]
  gpio4.IO[12]
  gpio4.IO[13]
  gpio4.IO[14]
  gpio4.IO[15]
  gpio4.IO[16]
  gpio2.IO[16]
  gpio2.IO[17]
  gpio2.IO[18]
  gpio2.IO[19]
  gpio2.IO[20]
  gpio2.IO[21]
  gpio4.IO[17]
  gpio4.IO[18]
  gpio4.IO[19]
  gpio4.IO[20]
  gpio4.IO[21]
  gpio4.IO[22]
  gpio4.IO[23]
  gpio4.IO[24]
  gpio4.IO[25]
  gpio4.IO[26]
  gpio4.IO[27]
  gpio4.IO[28]
- sdma.EXT_EVENT[0]
  sdma.EXT_EVENT[1]
  mqs.RIGHT
  mqs.LEFT
  osc32k.32K_OUT
  anatop.24M_OUT
  enet1.1588_EVENT0_IN
  enet1.1588_EVENT0_OUT
  sdma.EXT_EVENT[0]
  ccm.DI0_EXT_CLK
  enet2.1588_EVENT0_IN
  enet2.1588_EVENT0_OUT
  ccm.WAIT
  ccm.STOP
  ccm.PMIC_RDY
  usdhc1.RESET_B
  anatop.USBPHY1_TSTI_TX_LS_MODE
  anatop.USBPHY1_TSTI_TX_HS_MODE
  anatop.USBPHY1_TSTI_TX_DN
  anatop.USBPHY1_TSTO_RX_SQUELCH
  anatop.USBPHY1_TSTO_RX_DISCON_DET
  anatop.USBPHY1_TSTO_RX_HS_RXD
  anatop.USBPHY2_TSTO_RX_FS_RXD
  anatop.USBPHY1_TSTO_RX_FS_RXD
  anatop.USBPHY1_TSTI_TX_DP
  anatop.USBPHY1_TSTI_TX_EN
  anatop.USBPHY1_TSTI_TX_HIZ
  anatop.USBPHY2_TSTO_RX_HS_RXD
  anatop.USBPHY1_TSTO_PLL_CLK20DIV
  anatop.USBPHY2_TSTO_PLL_CLK20DIV
  anatop.USBPHY2_TSTO_RX_SQUELCH
  anatop.USBPHY2_TSTO_RX_DISCON_DET
  kpp.ROW[0]
  kpp.COL[0]
  kpp.ROW[1]
  kpp.COL[1]
  kpp.ROW[2]
  kpp.COL[2]
  kpp.ROW[3]
  kpp.COL[3]
  kpp.ROW[4]
  kpp.COL[4]
  kpp.ROW[5]
  kpp.COL[5]
  kpp.ROW[6]
  kpp.COL[6]
  kpp.ROW[7]
  kpp.COL[7]
  ocotp_ctrl_wrapper.FUSE_LATCHED
  anatop.TESTI[0]
  anatop.TESTI[1]
  anatop.TESTI[2]
  anatop.TESTI[3]
  src.BT_CFG[0]
  src.BT_CFG[1]
  src.BT_CFG[2]
  src.BT_CFG[3]
  src.BT_CFG[4]
  src.BT_CFG[5]
  src.BT_CFG[6]
  src.BT_CFG[7]
  src.BT_CFG[8]
  src.BT_CFG[9]
  src.BT_CFG[10]
  src.BT_CFG[11]
  src.BT_CFG[12]
  src.BT_CFG[13]
  src.BT_CFG[14]
  src.BT_CFG[15]
  src.BT_CFG[24]
  src.BT_CFG[25]
  src.BT_CFG[26]
  src.BT_CFG[27]
  src.BT_CFG[28]
  src.BT_CFG[29]
  src.BT_CFG[30]
  src.BT_CFG[31]
  anatop.TESTO[0]
  anatop.TESTO[1]
  anatop.TESTO[2]
  anatop.TESTO[3]
  anatop.TESTO[4]
  anatop.TESTO[5]
  anatop.TESTO[6]
  anatop.TESTO[7]
  anatop.TESTO[8]
  anatop.TESTO[9]
  anatop.TESTO[10]
  anatop.TESTO[11]
  anatop.TESTO[12]
  anatop.TESTO[13]
  anatop.TESTO[14]
  anatop.TESTO[15]
  sdma.EXT_EVENT[1]
  sdma.EXT_EVENT[0]
  ccm.OUT0
  ccm.OUT1
  ccm.OUT2
  ccm.CLKO1
  ccm.CLKO2
  snvs_hp_wrapper.VIO_5_CTL
  snvs_hp_wrapper.VIO_5
  pwm7.OUT
  pwm8.OUT
  src.INT_BOOT
  sai1.MCLK
  sai1.RX_SYNC
  sai1.RX_BCLK
  sai1.TX_SYNC
  sai1.TX_BCLK
  sai1.RX_DATA
  sai1.TX_DATA
- src.SYSTEM_RESET
  src.EARLY_RESET
  src.ANY_PU_RESET
  src.TESTER_ACK
  ccm.PLL2_BYP
  ccm.PLL3_BYP
  ccm.REF_EN_B
  ecspi1.TESTER_TRIGGER
  ecspi2.TESTER_TRIGGER
  ecspi3.TESTER_TRIGGER
  ecspi4.TESTER_TRIGGER
  usdhc1.TESTER_TRIGGER
  usdhc2.TESTER_TRIGGER
  qspi.TESTER_TRIGGER
  rawnand.TESTER_TRIGGER
  sjc.DONE
  sjc.DE_B
  sjc.FAIL
  sjc.JTAG_ACT
  sim_m.HADDR[0]
  sim_m.HADDR[1]
  sim_m.HADDR[2]
  sim_m.HADDR[3]
  sim_m.HADDR[4]
  sim_m.HADDR[5]
  sim_m.HADDR[6]
  sim_m.HADDR[7]
  sim_m.HADDR[8]
  sim_m.HADDR[9]
  sim_m.HADDR[10]
  sim_m.HADDR[11]
  sim_m.HADDR[12]
  sim_m.HADDR[13]
  sim_m.HADDR[14]
  sim_m.HADDR[15]
  sim_m.HADDR[16]
  sim_m.HADDR[17]
  sim_m.HADDR[18]
  sim_m.HADDR[19]
  sim_m.HADDR[20]
  sim_m.HADDR[21]
  sim_m.HADDR[22]
  sim_m.HADDR[23]
  sim_m.HADDR[24]
  sim_m.HADDR[25]
  sim_m.HADDR[26]
  sim_m.HADDR[27]
  sim_m.HADDR[28]
  sim_m.HADDR[29]
  sim_m.HADDR[30]
  sim_m.HADDR[31]
  sim_m.HBURST[0]
  sim_m.HBURST[1]
  sim_m.HBURST[2]
  sim_m.HMASTLOCK
  sim_m.HPROT[0]
  sim_m.HPROT[1]
  sim_m.HPROT[2]
  sim_m.HPROT[3]
  sim_m.HREADYOUT
  sim_m.HRESP
  sim_m.HSIZE[0]
  sim_m.HSIZE[1]
  sim_m.HSIZE[2]
  sim_m.HWRITE
  tpsmp.CLK
  tpsmp.HDATA_DIR
  tpsmp.HTRANS[0]
  tpsmp.HTRANS[1]
  tpsmp.HDATA[0]
  tpsmp.HDATA[1]
  tpsmp.HDATA[2]
  tpsmp.HDATA[3]
  tpsmp.HDATA[4]
  tpsmp.HDATA[5]
  tpsmp.HDATA[6]
  tpsmp.HDATA[7]
  tpsmp.HDATA[8]
  tpsmp.HDATA[9]
  tpsmp.HDATA[10]
  tpsmp.HDATA[11]
  tpsmp.HDATA[12]
  tpsmp.HDATA[13]
  tpsmp.HDATA[14]
  tpsmp.HDATA[15]
  tpsmp.HDATA[16]
  tpsmp.HDATA[19]
  tpsmp.HDATA[17]
  tpsmp.HDATA[18]
  observe_mux.OUT[0]
  observe_mux.OUT[1]
  observe_mux.OUT[2]
  observe_mux.OUT[3]
  observe_mux.OUT[4]
  tpsmp.HDATA[20]
  tpsmp.HDATA[21]
  tpsmp.HDATA[22]
  tpsmp.HDATA[23]
  tpsmp.HDATA[24]
  tpsmp.HDATA[25]
  tpsmp.HDATA[26]
  tpsmp.HDATA[27]
  tpsmp.HDATA[28]
  tpsmp.HDATA[29]
  tpsmp.HDATA[30]
  tpsmp.HDATA[31]
- epit1.OUT
  epit2.OUT
  wdog3.WDOG_B
  wdog1.WDOG_B
  uart1.TX
  uart1.RX
  uart5.TX
  uart5.RX
  uart1.CTS_B
  uart1.RTS_B
  uart5.RTS_B
  uart5.CTS_B
  spdif.OUT
  spdif.IN
  usdhc2.WP
  usdhc2.CD_B
  ecspi3.SS0
  ecspi3.SCLK
  ecspi3.MOSI
  ecspi3.MISO
  anatop.OTG1_ID
  epit1.OUT
  epit2.OUT
  wdog1.WDOG_B
  ecspi2.SCLK
  ecspi2.SS0
  ecspi2.MOSI
  ecspi2.MISO
  usdhc1.LCTL
  usdhc2.LCTL
  usdhc1.VSELECT
  usdhc2.VSELECT
  wdog1.WDOG_RST_B_DEB
  wdog2.WDOG_RST_B_DEB
  gpt1.CLK
  gpt1.CAPTURE2
  usb.OTG1_PWR
  usb.OTG1_OC
  anatop.ENET_REF_CLK_25M
  anatop.24M_OUT
  usb.OTG2_PWR
  usb.OTG2_OC
  anatop.OTG2_ID
  global wdog
  wdog1.WDOG_RST_B_DEB
  ecspi2.RDY
  ecspi2.SS1
  ecspi2.SS2
  ecspi2.SS3
  sai1.MCLK
  sai1.TX_SYNC
  sai1.TX_BCLK
  sai1.RX_DATA
  sai1.TX_DATA
  ecspi1.SS1
  ecspi1.SS2
  ecspi1.SS3
  can1.TX
  can1.RX
  can2.TX
  can2.RX
  ecspi1.RDY
  usdhc2.RESET_B
  usdhc2.DATA4
  usdhc2.DATA5
  usdhc2.DATA6
  usdhc2.DATA7
  usdhc2.CMD
  usdhc2.CLK
  usdhc2.DATA0
  usdhc2.DATA1
  usdhc2.DATA2
  usdhc2.DATA3
  ecspi3.SS2
  ecspi3.SS3
  ecspi4.RDY
  ecspi4.SS1
  ecspi4.SS2
  ecspi4.SS3
  uart2.TX
  uart2.RX
  uart2.CTS_B
  uart2.RTS_B
  ecspi3.SS1
  ecspi3.RDY
  uart3.TX
  uart3.RX
  uart3.CTS_B
  uart3.RTS_B
  spdif.EXT_CLK
  usb.OTG1_PWR
  usb.OTG1_OC
  anatop.OTG1_ID
  usb.OTG2_PWR
  usb.OTG2_OC
  anatop.OTG2_ID
  uart6.TX
  uart6.RX
  uart6.RTS_B
  uart6.CTS_B
  uart5.TX
  uart5.RX
  uart5.RTS_B
  uart5.CTS_B
  usdhc1.WP
  usdhc1.CD_B
  usdhc1.RESET_B
  usdhc1.VSELECT
- uart5.TX
  uart5.RX
  uart5.CTS_B
  uart5.RTS_B
  epdc.PWRCTRL[1]
  epdc.PWRCTRL[2]
  epdc.PWRCTRL[3]
  epdc.SDCE[4]
  epdc.SDCE[5]
  epdc.SDCE[6]
  epdc.SDCE[7]
  epdc.SDCE[8]
  epdc.SDCE[9]
  epdc.SDOED
  epdc.SDOEZ
  epdc.SDDO[8]
  epdc.SDDO[9]
  epdc.SDDO[10]
  epdc.SDDO[11]
  epdc.SDDO[12]
  epdc.SDDO[13]
  epdc.SDDO[14]
  epdc.SDDO[15]
  epdc.SDCLK
  epdc.SDLE
  epdc.SDOE
  epdc.SDCE[0]
  epdc.GDOE
  epdc.SDDO[0]
  epdc.SDDO[1]
  epdc.SDDO[2]
  epdc.SDDO[3]
  epdc.SDDO[4]
  epdc.SDDO[5]
  epdc.SDDO[6]
  epdc.SDDO[7]
  epdc.PWRIRQ
  epdc.PWRWAKE
  epdc.PWRCOM
  epdc.PWRSTAT
  epdc.PWRCTRL[0]
  epdc.BDR[0]
  epdc.SDSHR
  epdc.GDRL
  epdc.GDCLK
  epdc.GDSP
  epdc.BDR[1]
  epdc.VCOM[0]
  epdc.VCOM[1]
  epdc.SDCE[1]
  epdc.SDCE[2]
  epdc.SDCE[3]
  esai.TX3_RX2
  esai.TX2_RX3
  esai.TX4_RX1
  esai.TX1
  esai.TX_HF_CLK
  esai.RX_HF_CLK
  esai.RX_FS
  esai.RX_CLK
  esai.TX_FS
  esai.TX_CLK
  esai.TX5_RX0
  esai.TX0
- 100K PD
  100K PU
  100K PU
  100K PU
  100K PD
  100K PD
  100K PD
  Keeper
  Keeper
  Keeper
  Keeper
  Keeper
  Keeper
  Keeper
  Keeper
  Keeper
  Keeper
  100K PU
  47K PU
  100K PU
  47K PU
  47K PU
  47K PU
  Keeper
  Keeper
  Keeper
  Keeper
  Keeper
  Keeper
  Keeper
  Keeper
  Keeper
  Keeper
  Keeper
  Keeper
  Keeper
  Keeper
  Keeper
  Keeper
  Keeper
  Keeper
  Keeper
  Keeper
  Keeper
  Keeper
  Keeper
  Keeper
  Keeper
  Keeper
  Keeper
  Keeper
  Keeper
  Keeper
  Keeper
  Keeper
  Keeper
  Keeper
  Keeper
  Keeper
  Keeper
  Keeper
  Keeper
  Keeper
  Keeper
  Keeper
  Keeper
  Keeper
  Keeper
  Keeper
  Keeper
  Keeper
  Keeper
  Keeper
  Keeper
  Keeper
  Keeper
  Keeper
  Keeper
  Keeper
  Keeper
  Keeper
  Keeper
  Keeper
  Keeper
  Keeper
  Keeper
  Keeper
  Keeper
  Keeper
  Keeper
  Keeper
  Keeper
  Keeper
  Keeper
  Keeper
  Keeper
  Keeper
  Keeper
  Keeper
  Keeper
  Keeper
  Keeper
  Keeper
  Keeper
  Keeper
  Keeper
  Keeper
  Keeper
  Keeper
  Keeper
  Keeper
  Keeper
  Keeper
  Keeper
  Keeper
  Keeper
  Keeper
  Keeper
  Keeper
  Keeper
  Keeper
  Keeper
  Keeper
  Keeper
  Keeper
  Keeper
  Keeper
  Keeper
  Keeper
sheet 3
- Default:
- DC12V
- ME6239A33M3G:
- SNVS_3V3
- SOM6Y08
- 12V@2A
- 3.3V@0.2A
- EUP3484:
- VDD5V
- PMOS
- VCC5V
- USB
- 5V@3A
- 5V@2A
- LCD
- AUDIO
- TLV62569:
- 4G
- 3.8V@2A
- 隔离模块
- ISO_5V(RS485、RS232、CAN)
- 5V@0.5A
- SY8089AAC:
- SYS_3V3
- UART1
- 3.3V@2A
- ETHERNET2
- USB_HUB
- SOM6Y08
- SD
- RTC
- WIFI
sheet 4
- USB2.0
- USB2514
- USB X 4
- 4G(EC20)
- WIFI(ATBM6032I)
- USB2.0 X 2
- GPIO1
- JTAG/CODEC
- USBOTG1
- USBOTG2
- SD1
- UART1
- TFCARD
- RS232 X 2
- SP3232EEN-L/TR
- UART
- UART1
- UART2
- GPIO X 10
- 扩展接口
- UART3
- UART4
- UART5
- 6Y08
- 2.54mm X 20
- SP485EEN-L/TR
- CAN1
- RS485 X 2
- SNVS_GPIO
- TJA1057GT/3J
- CAN
- KSZ8081
- ENET2
- CSI
- GPIO4
- RJ45 X 2
- CSI
- SPI1
- I2C X 2
- ETH1
- LCD
- SPI
- 扩展接口(2.54mm X 15)
sheet 5
- SOM6ULX
- BMODE[1:0]
- BOOT TYPE
- 00
- Boot From Fuses
- 01
- Serial Downloader
- 10
- Internal Boot (Development)
- 11
- Reserved
- PD (100K)
- PD (100K)
sheet 6
- USB-OTG
- USB HUB
sheet 7
- ETHERNET
- CLOSE TO CPU
- CLOSE TO PHY
